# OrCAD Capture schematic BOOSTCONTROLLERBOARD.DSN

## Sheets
1 7 I2C Devices: size B; title: Controller Board: I2C Devices; rev: B; company: MBARI; note: 10021168
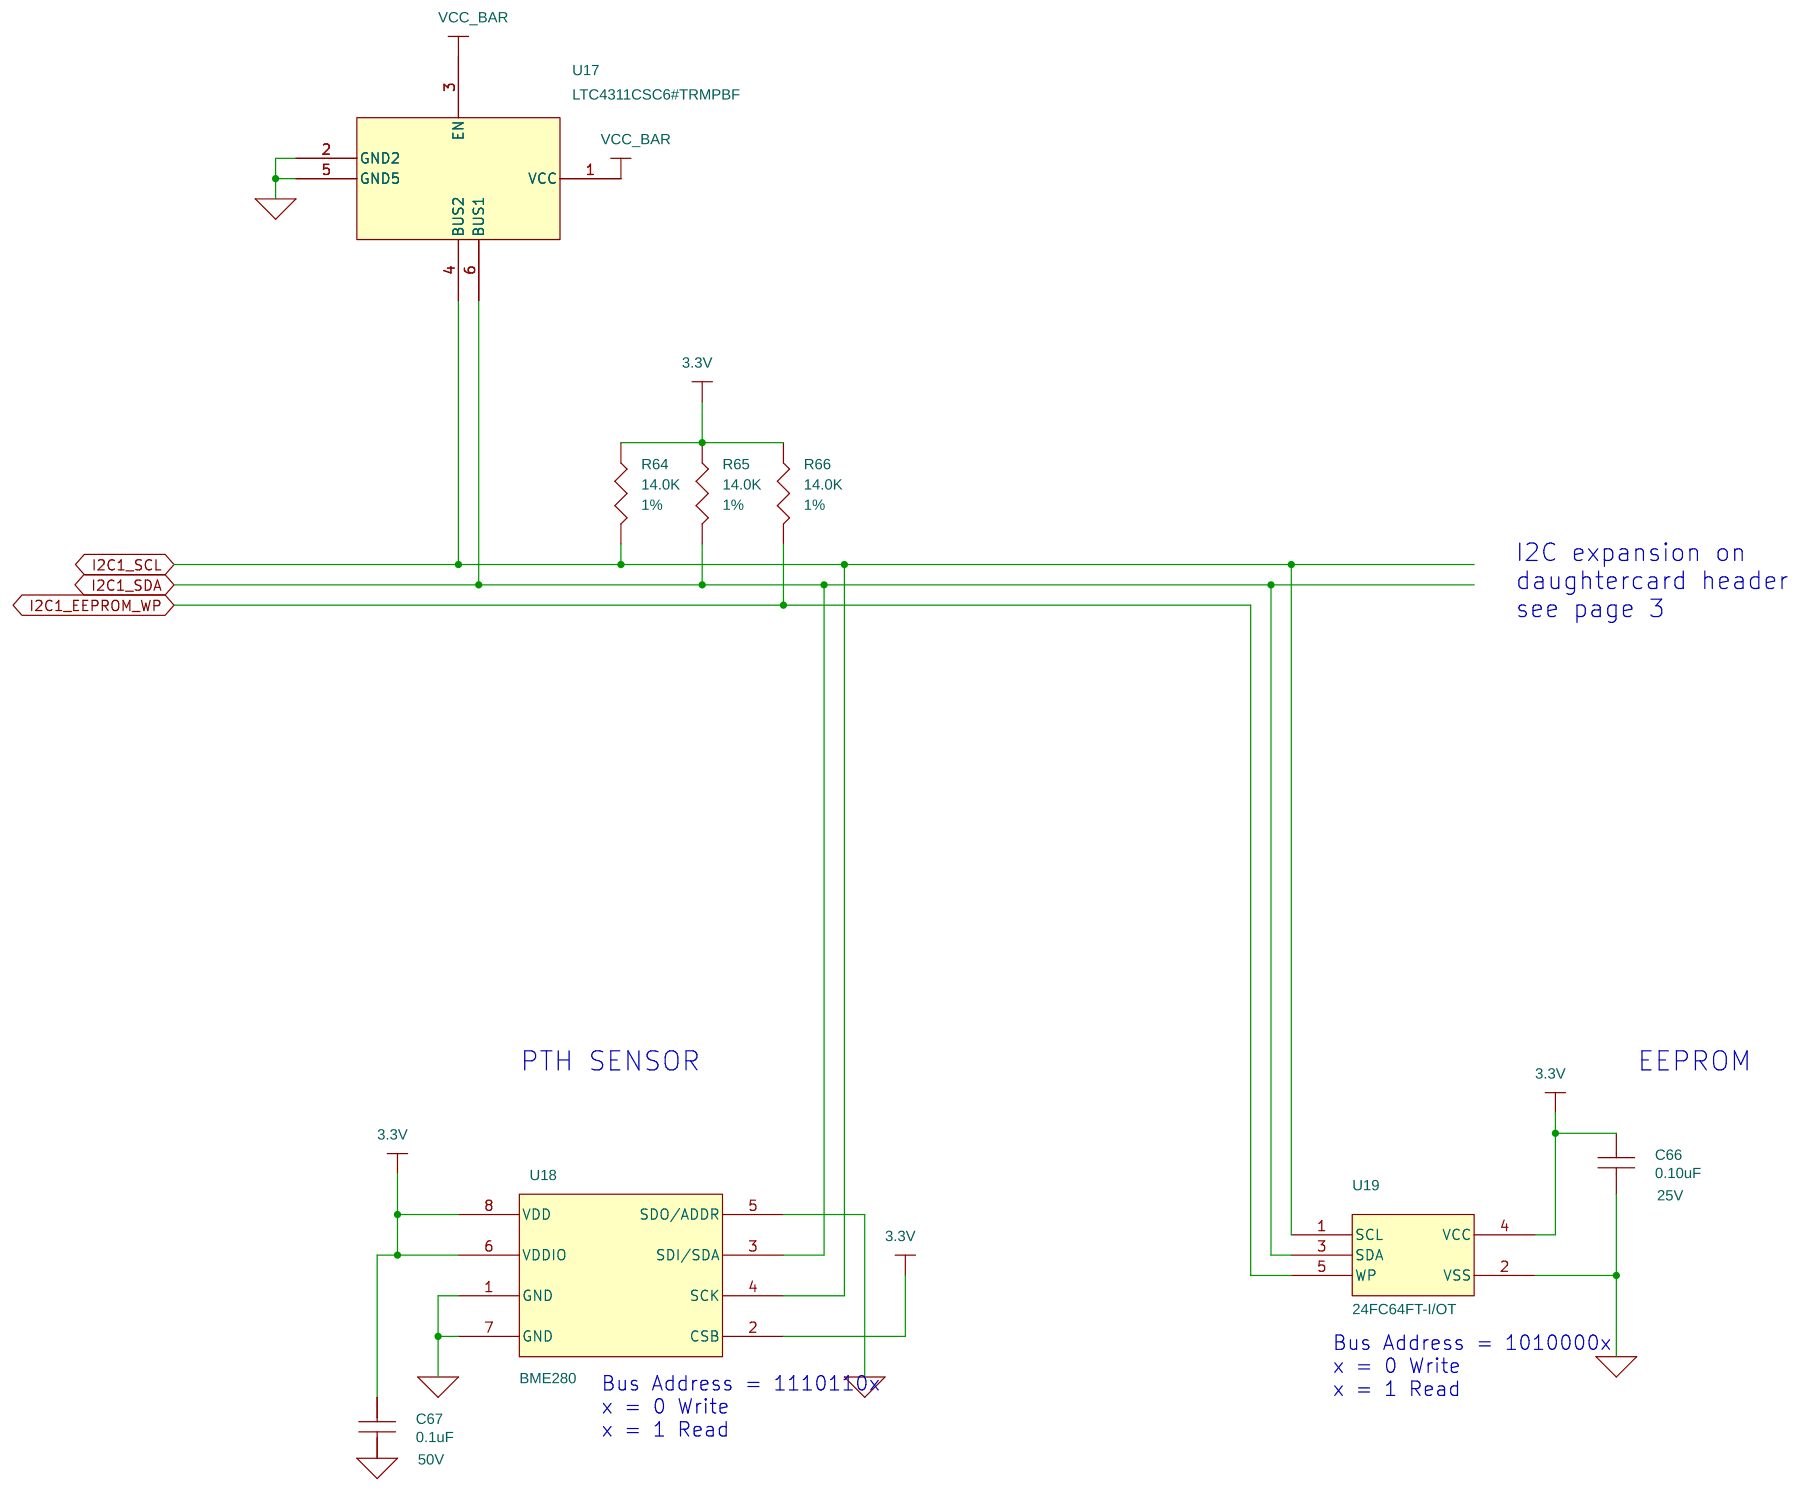
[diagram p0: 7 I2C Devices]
2 2 Power Supply: size C; title: Controller Board: Power Supply
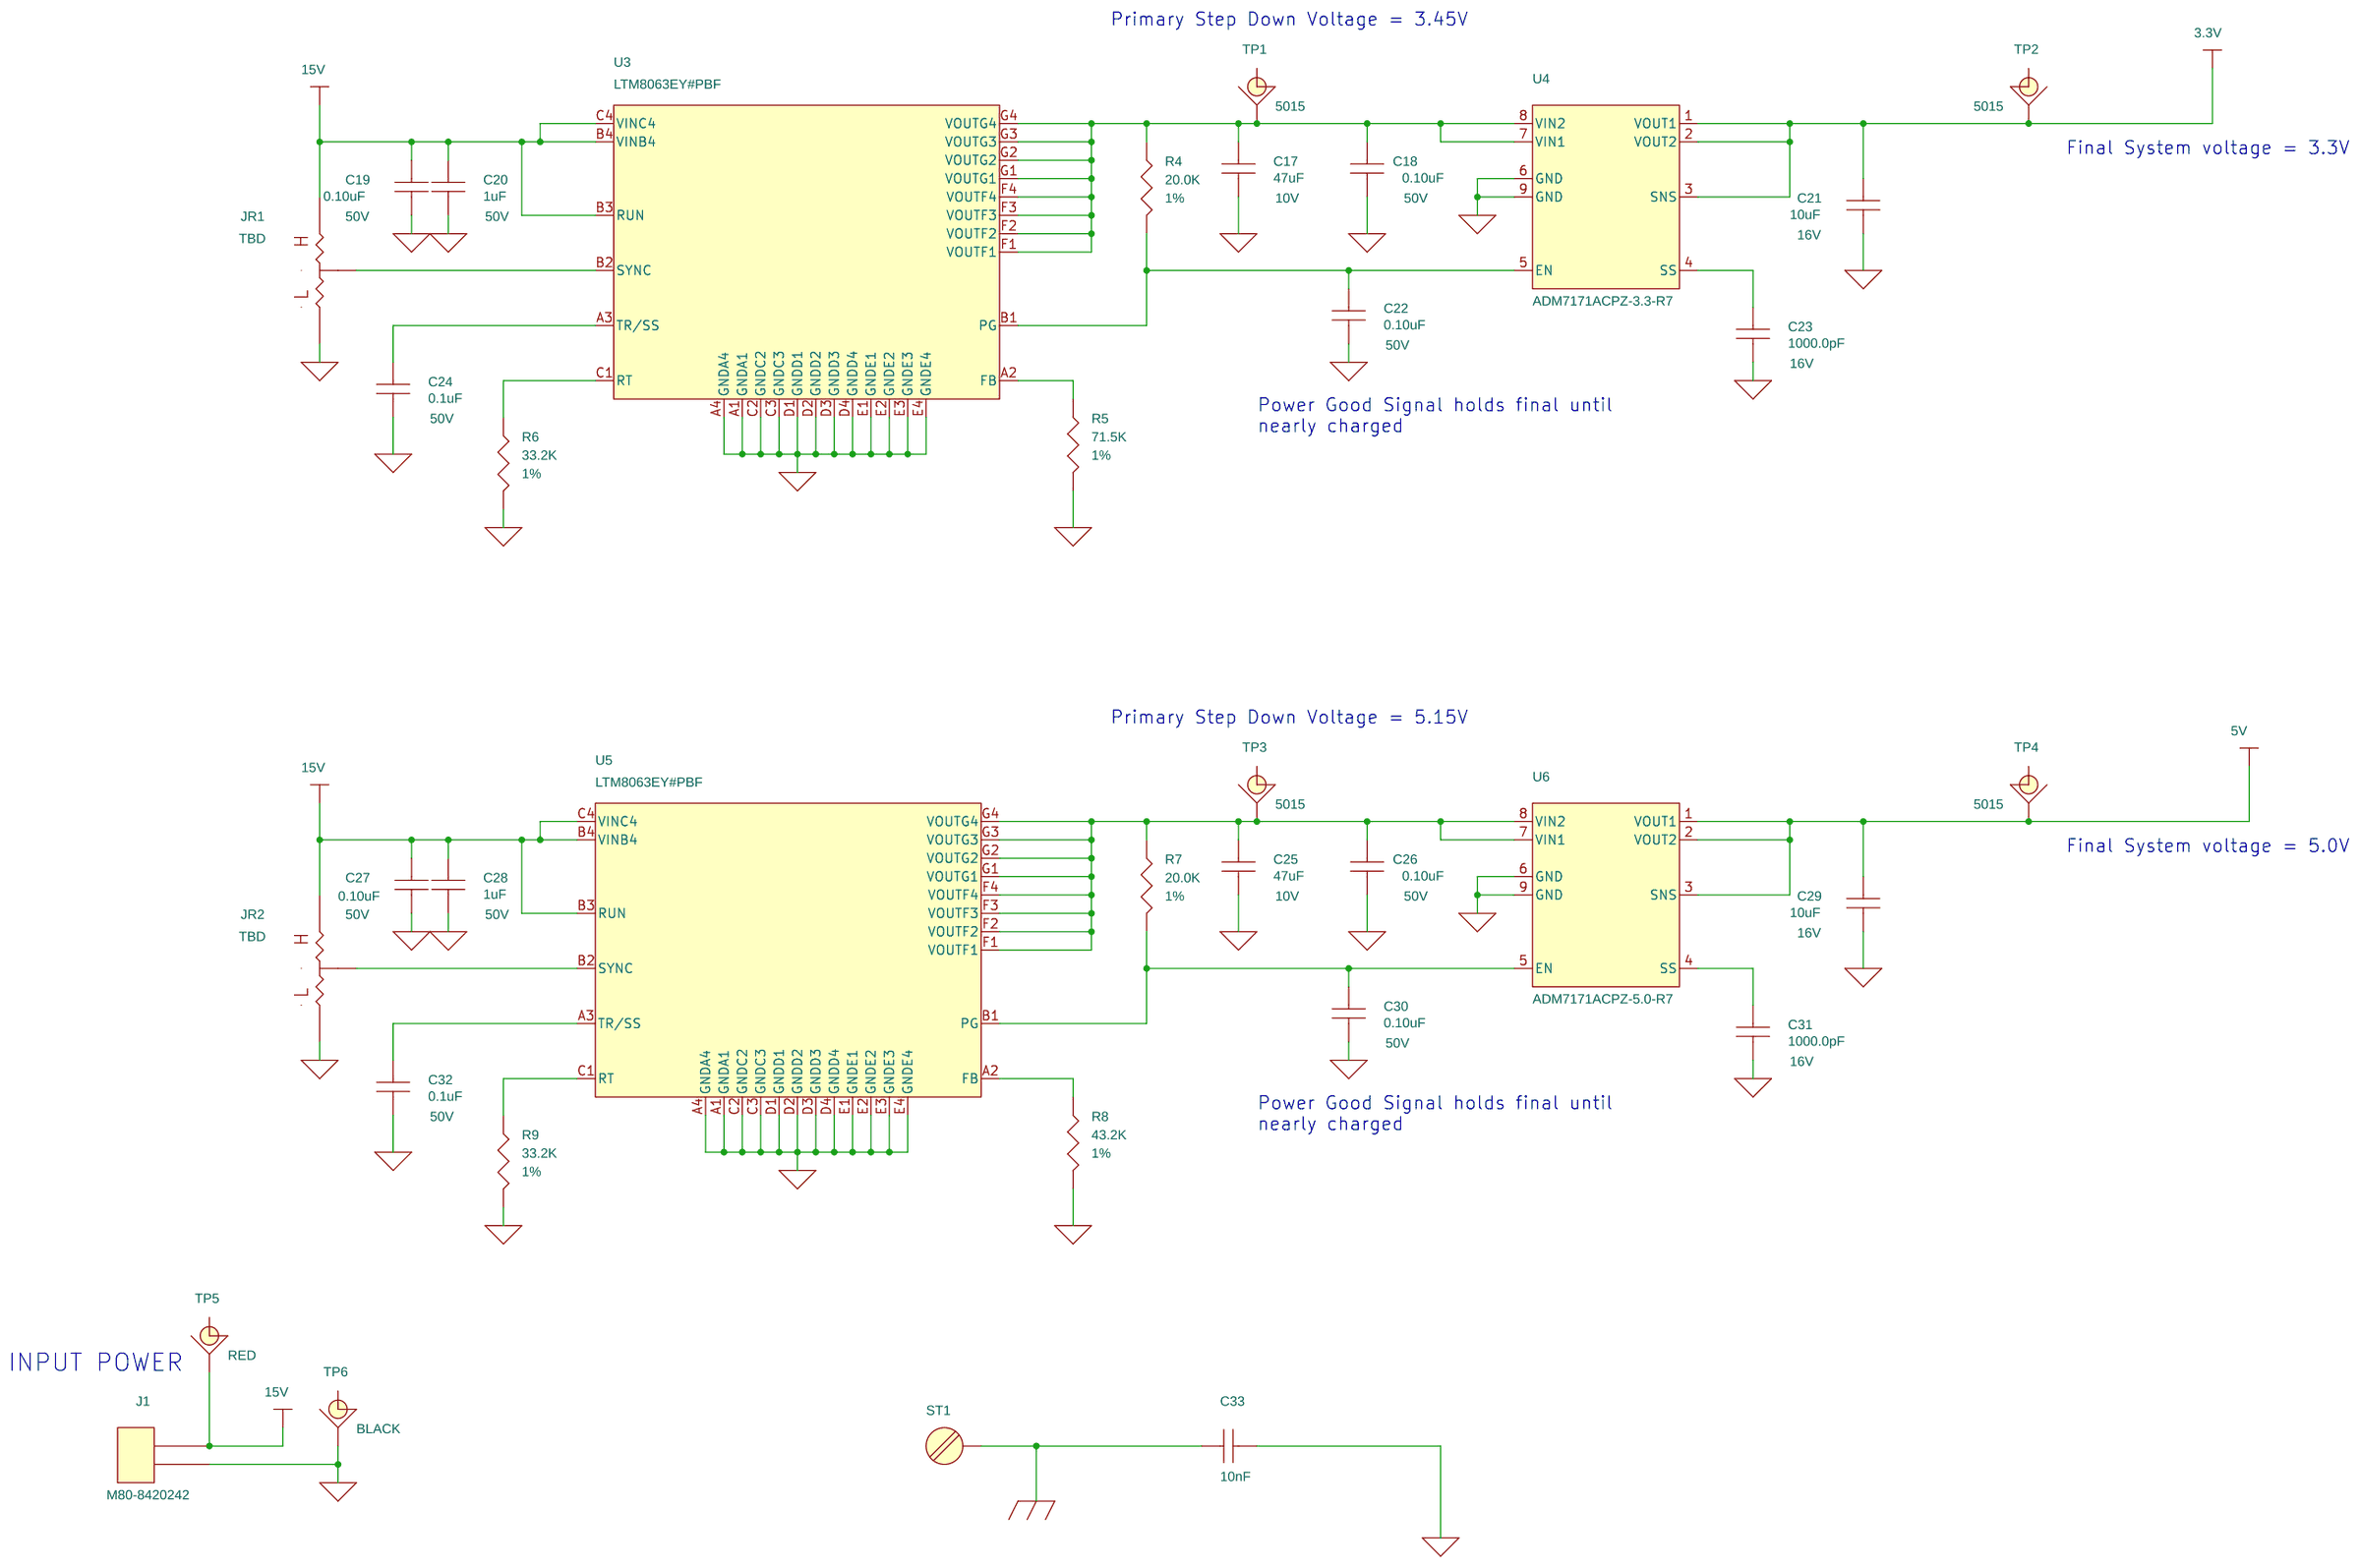
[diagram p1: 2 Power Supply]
3 1 Microcontroller: size Custom; title: Controller Board: Microcontroller
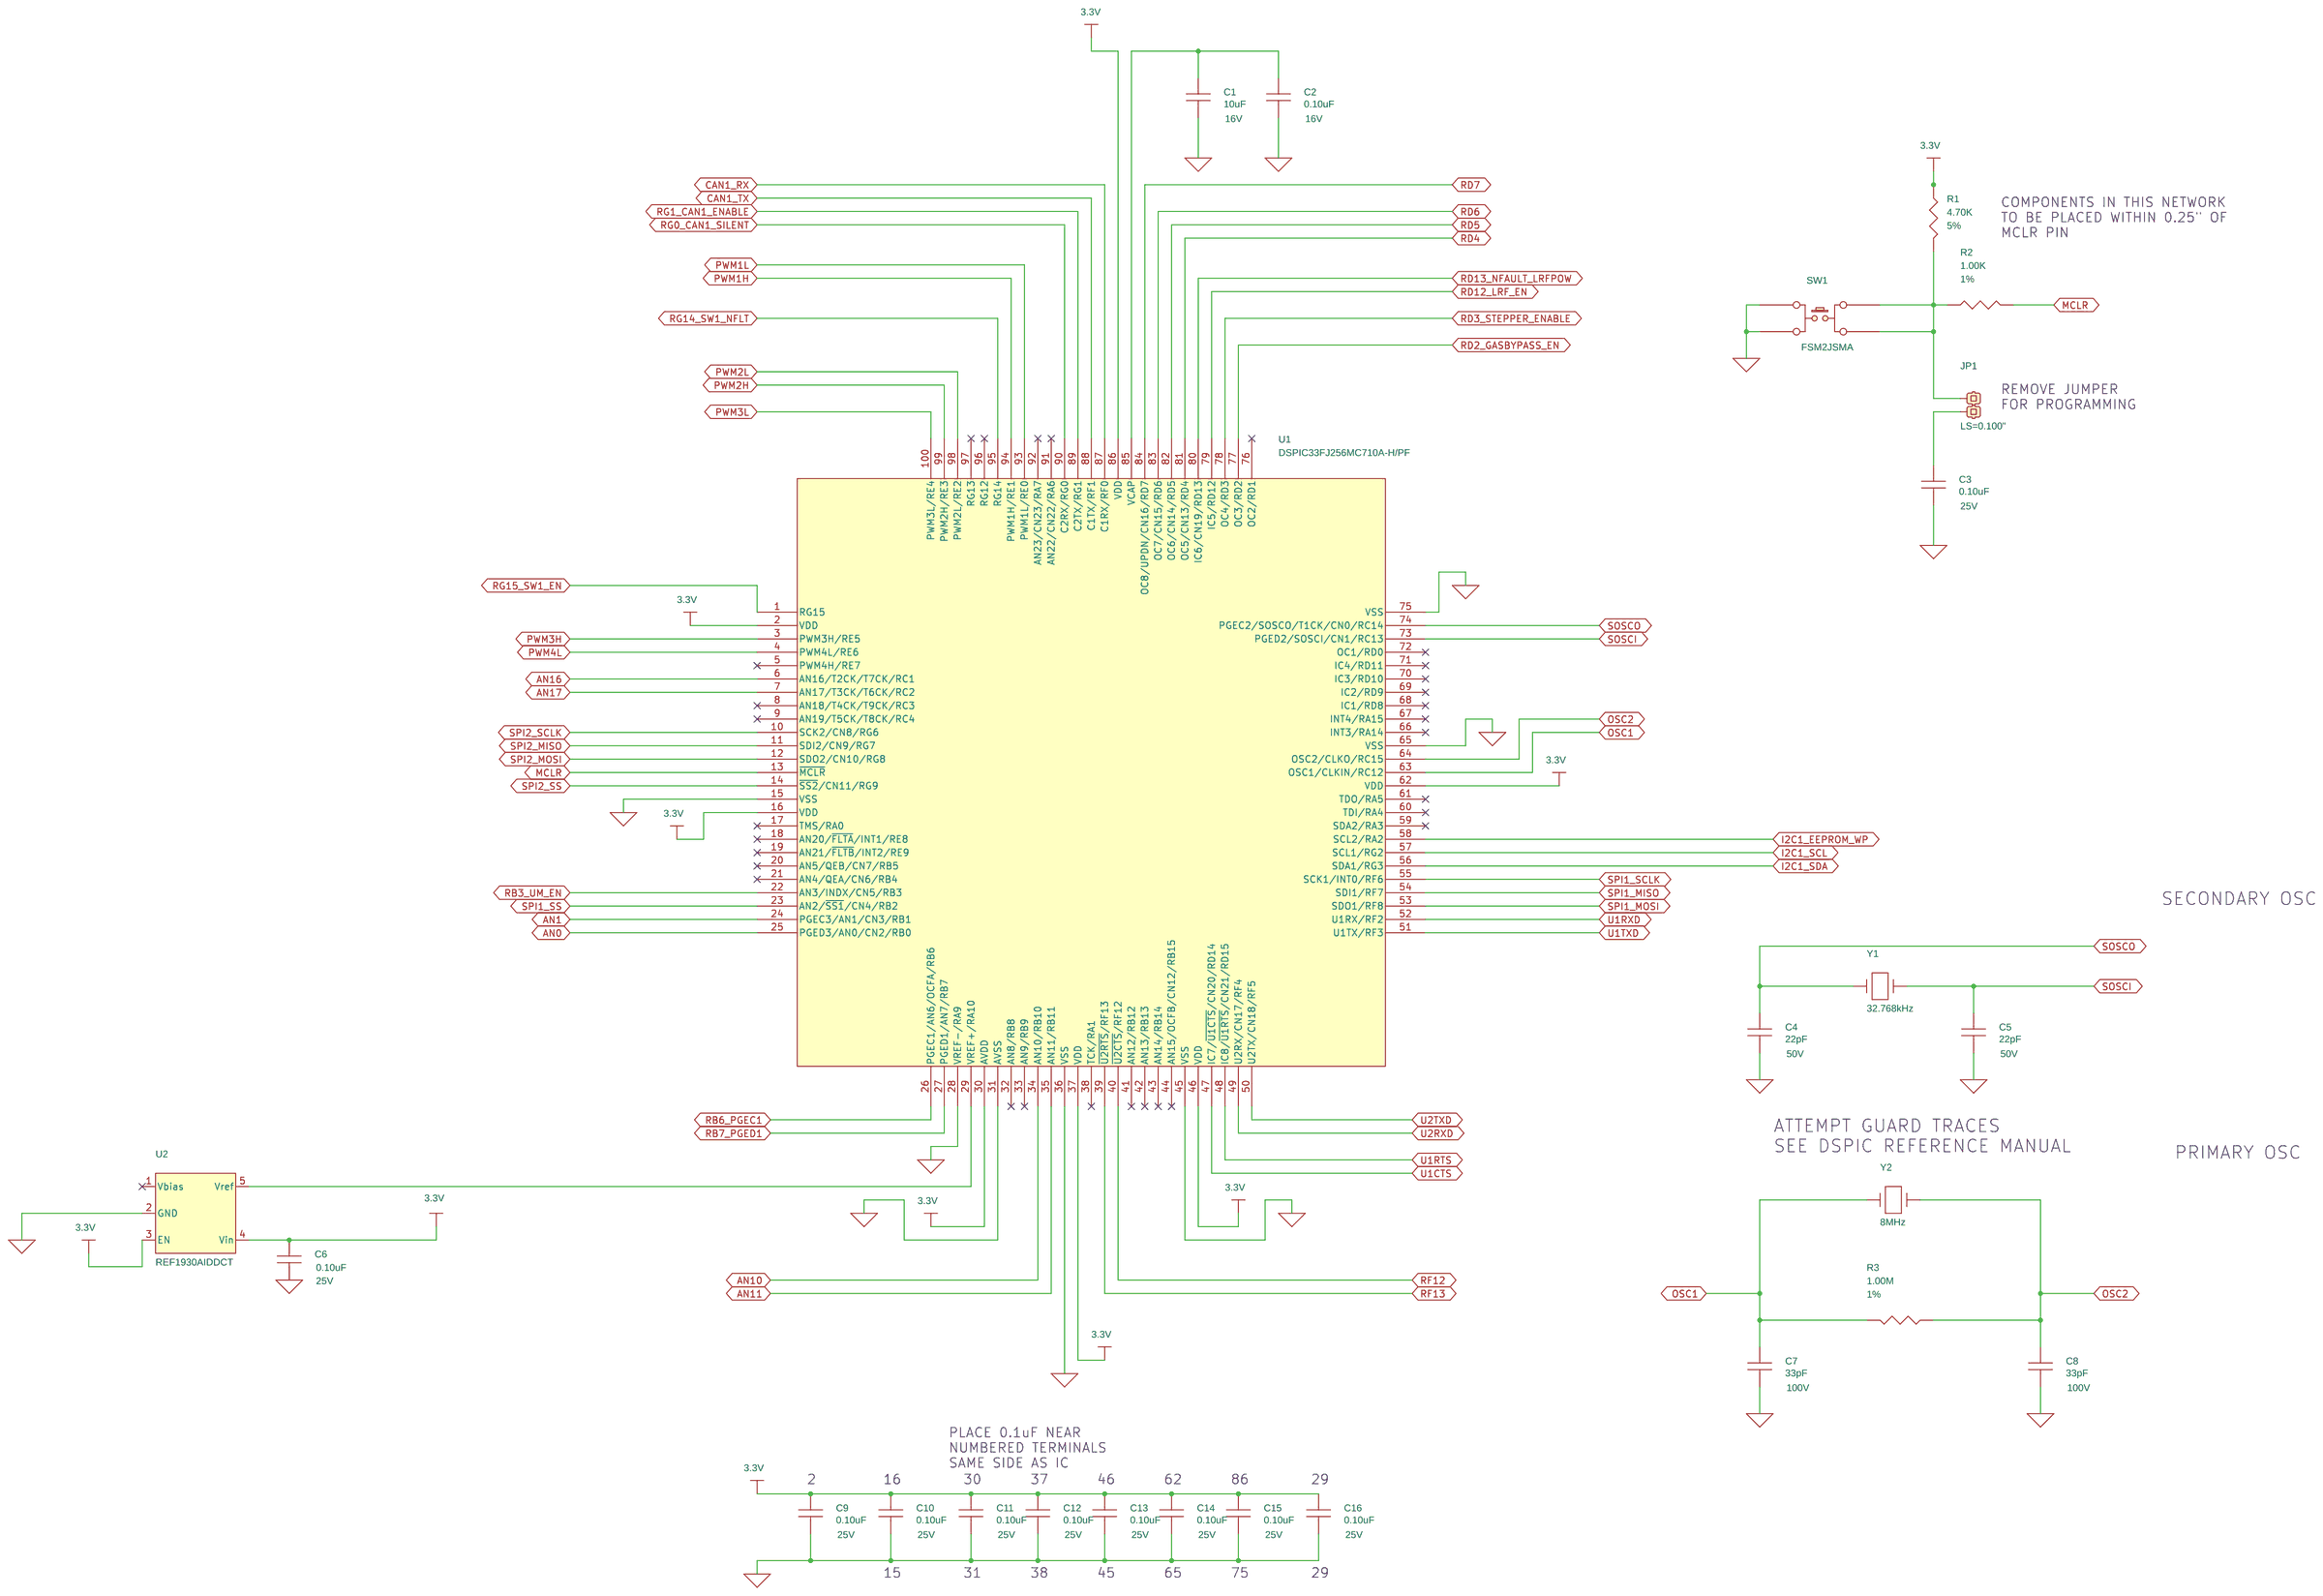
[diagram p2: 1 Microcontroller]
4 3 Telemetry: size Custom; title: Controller Board: Telemetry
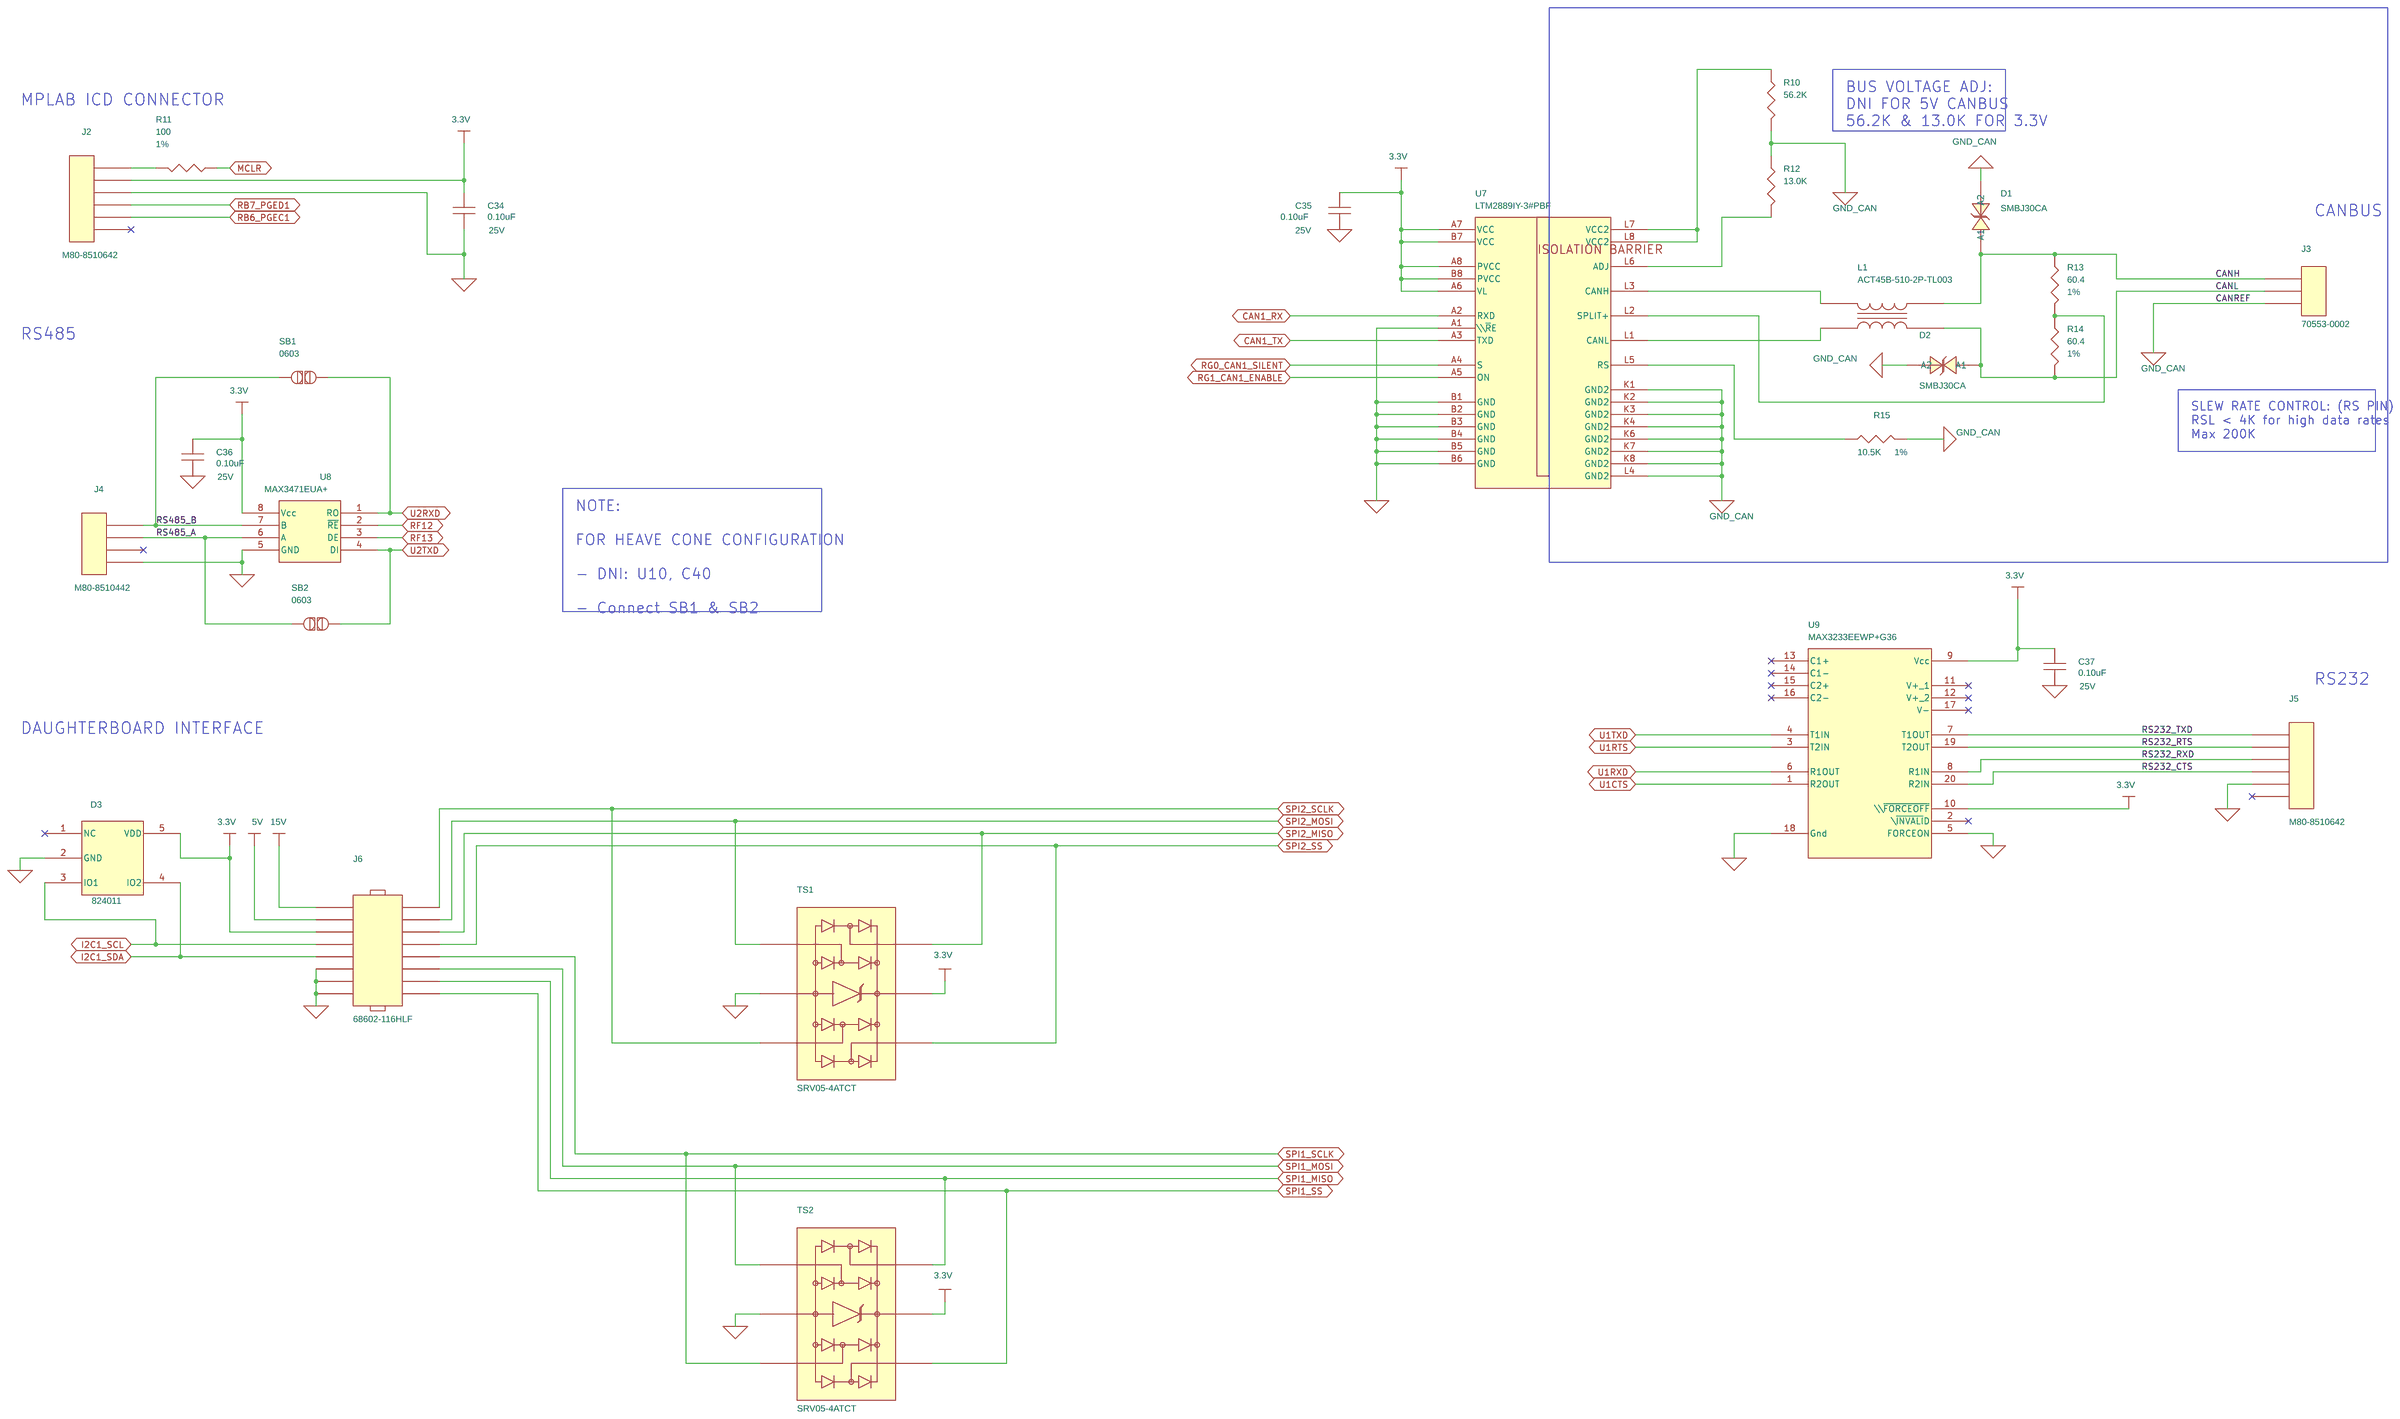
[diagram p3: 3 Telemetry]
5 5 Analog Inputs Sensors: size Custom; title: Controller Board: Sensor Inputs
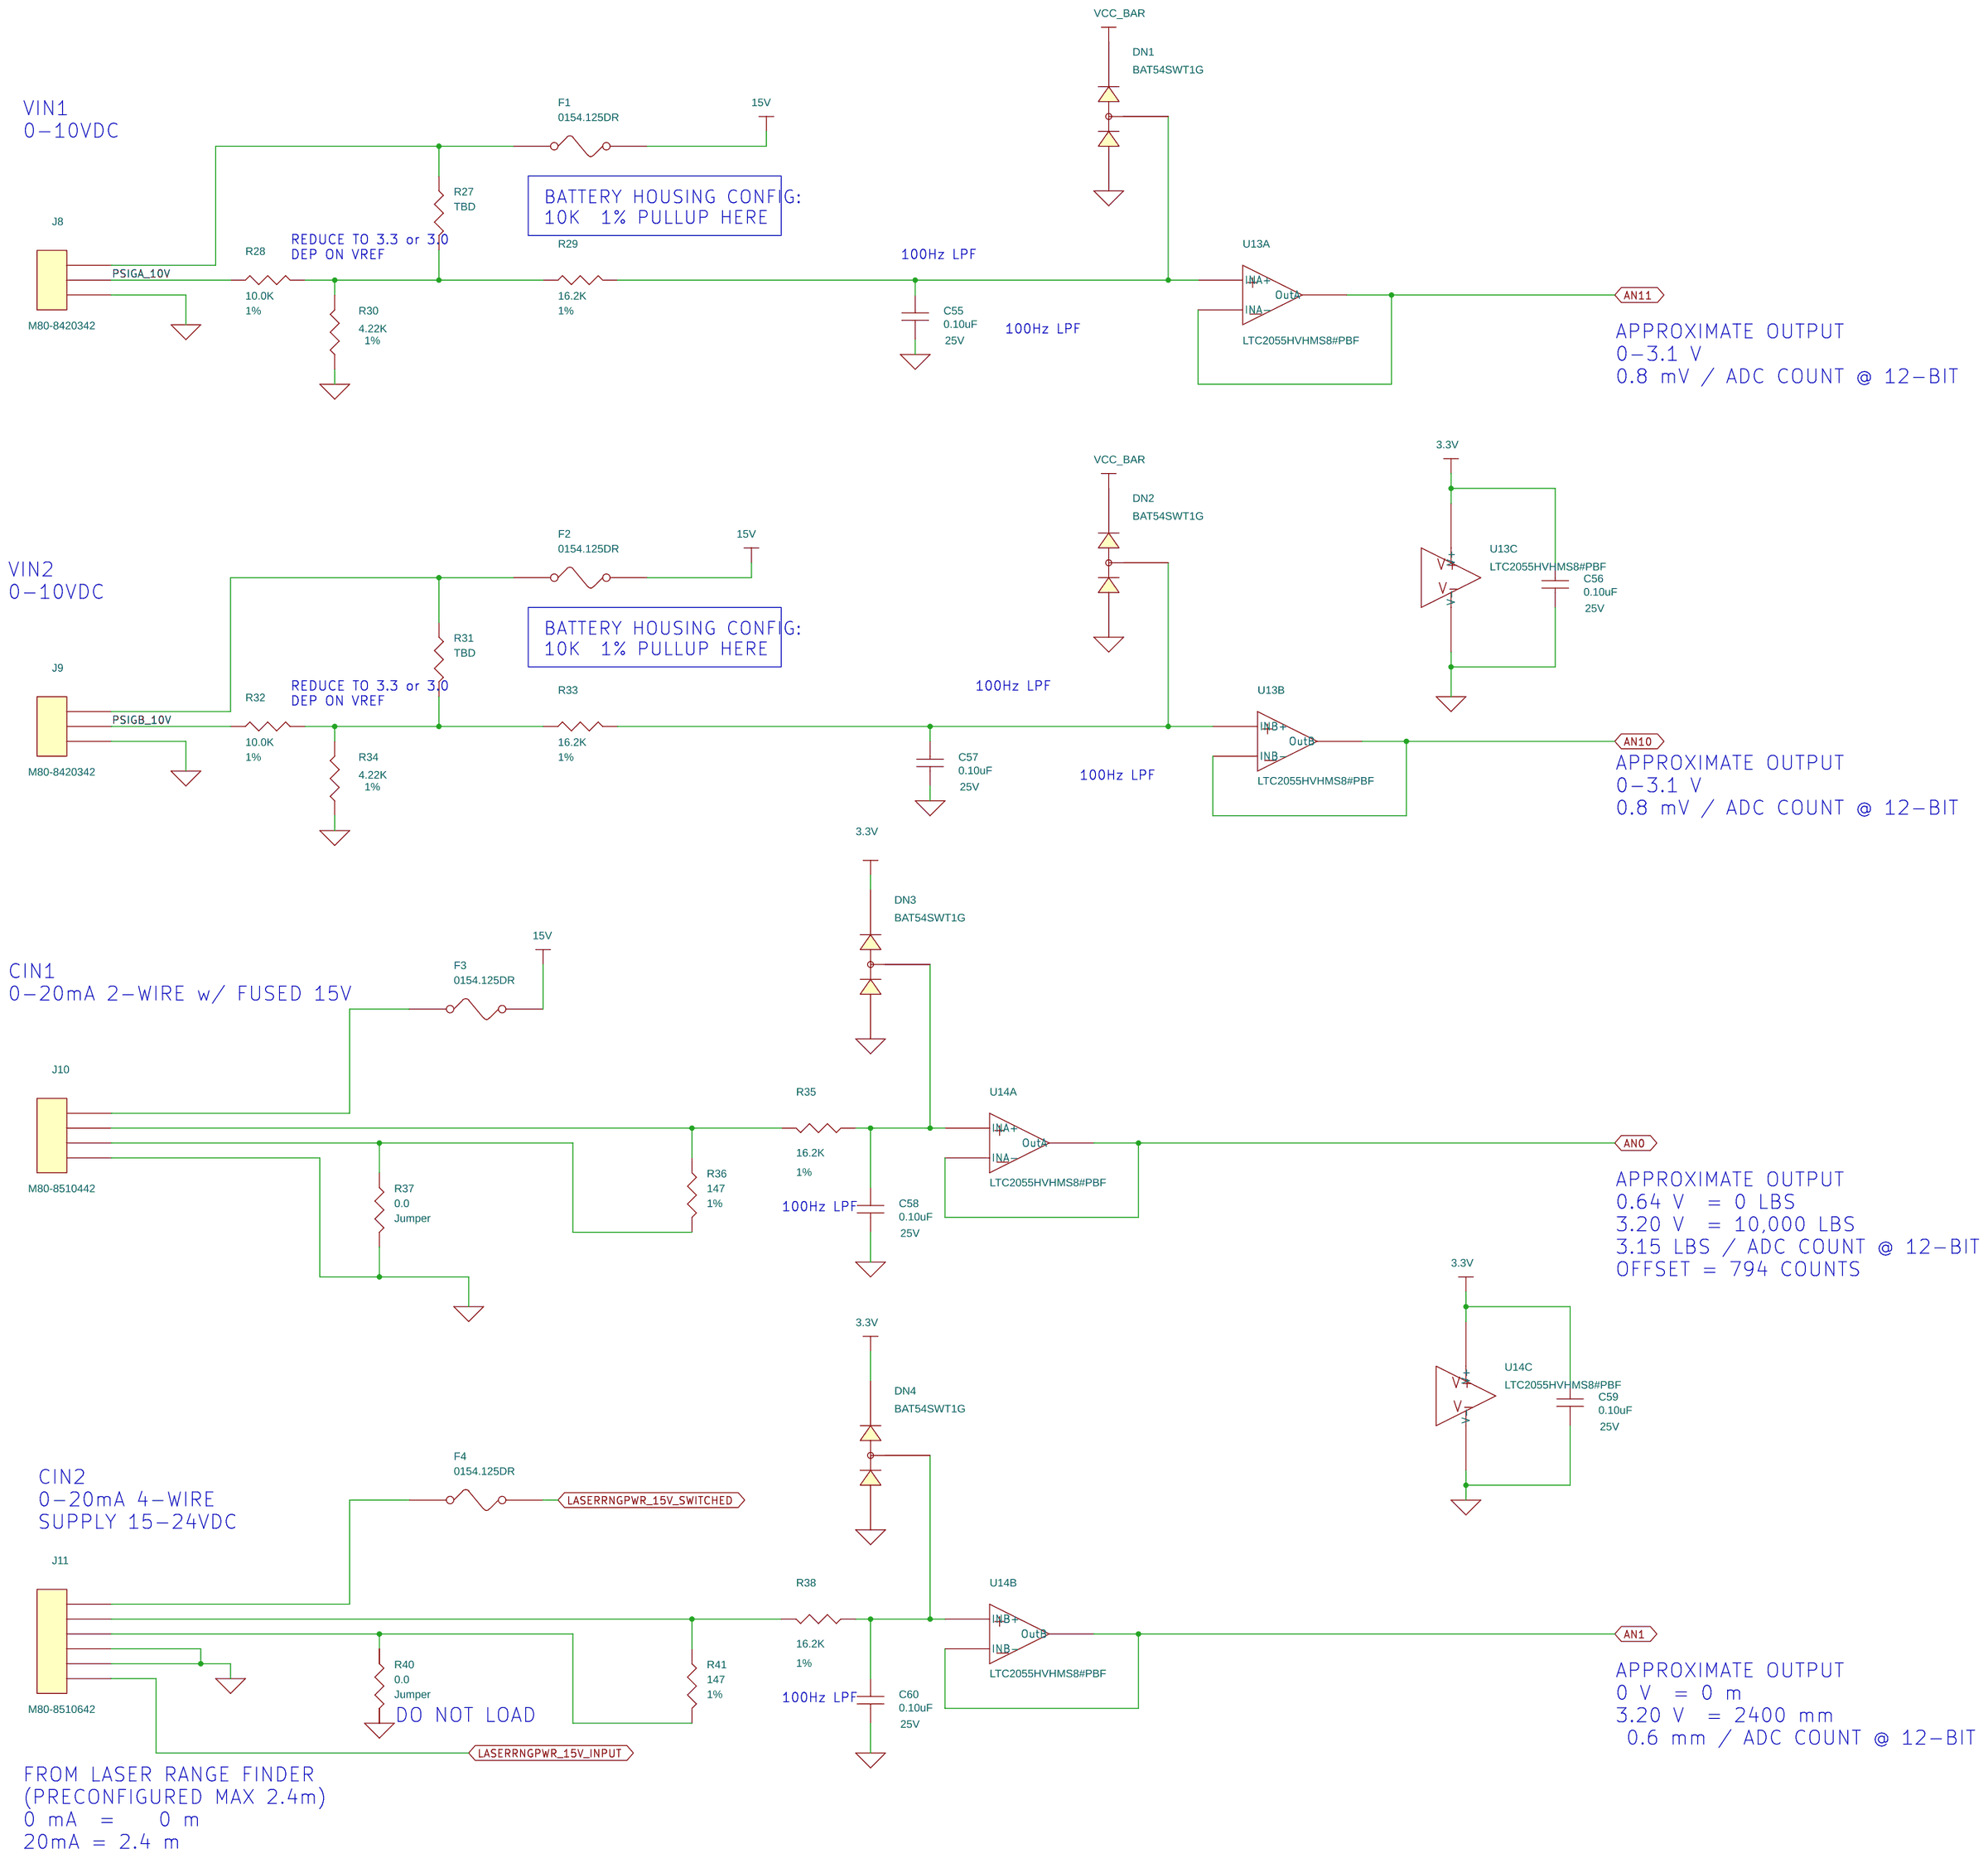
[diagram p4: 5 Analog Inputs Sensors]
6 6 Digital I/O: size Custom; title: Controller Board: Digital IO
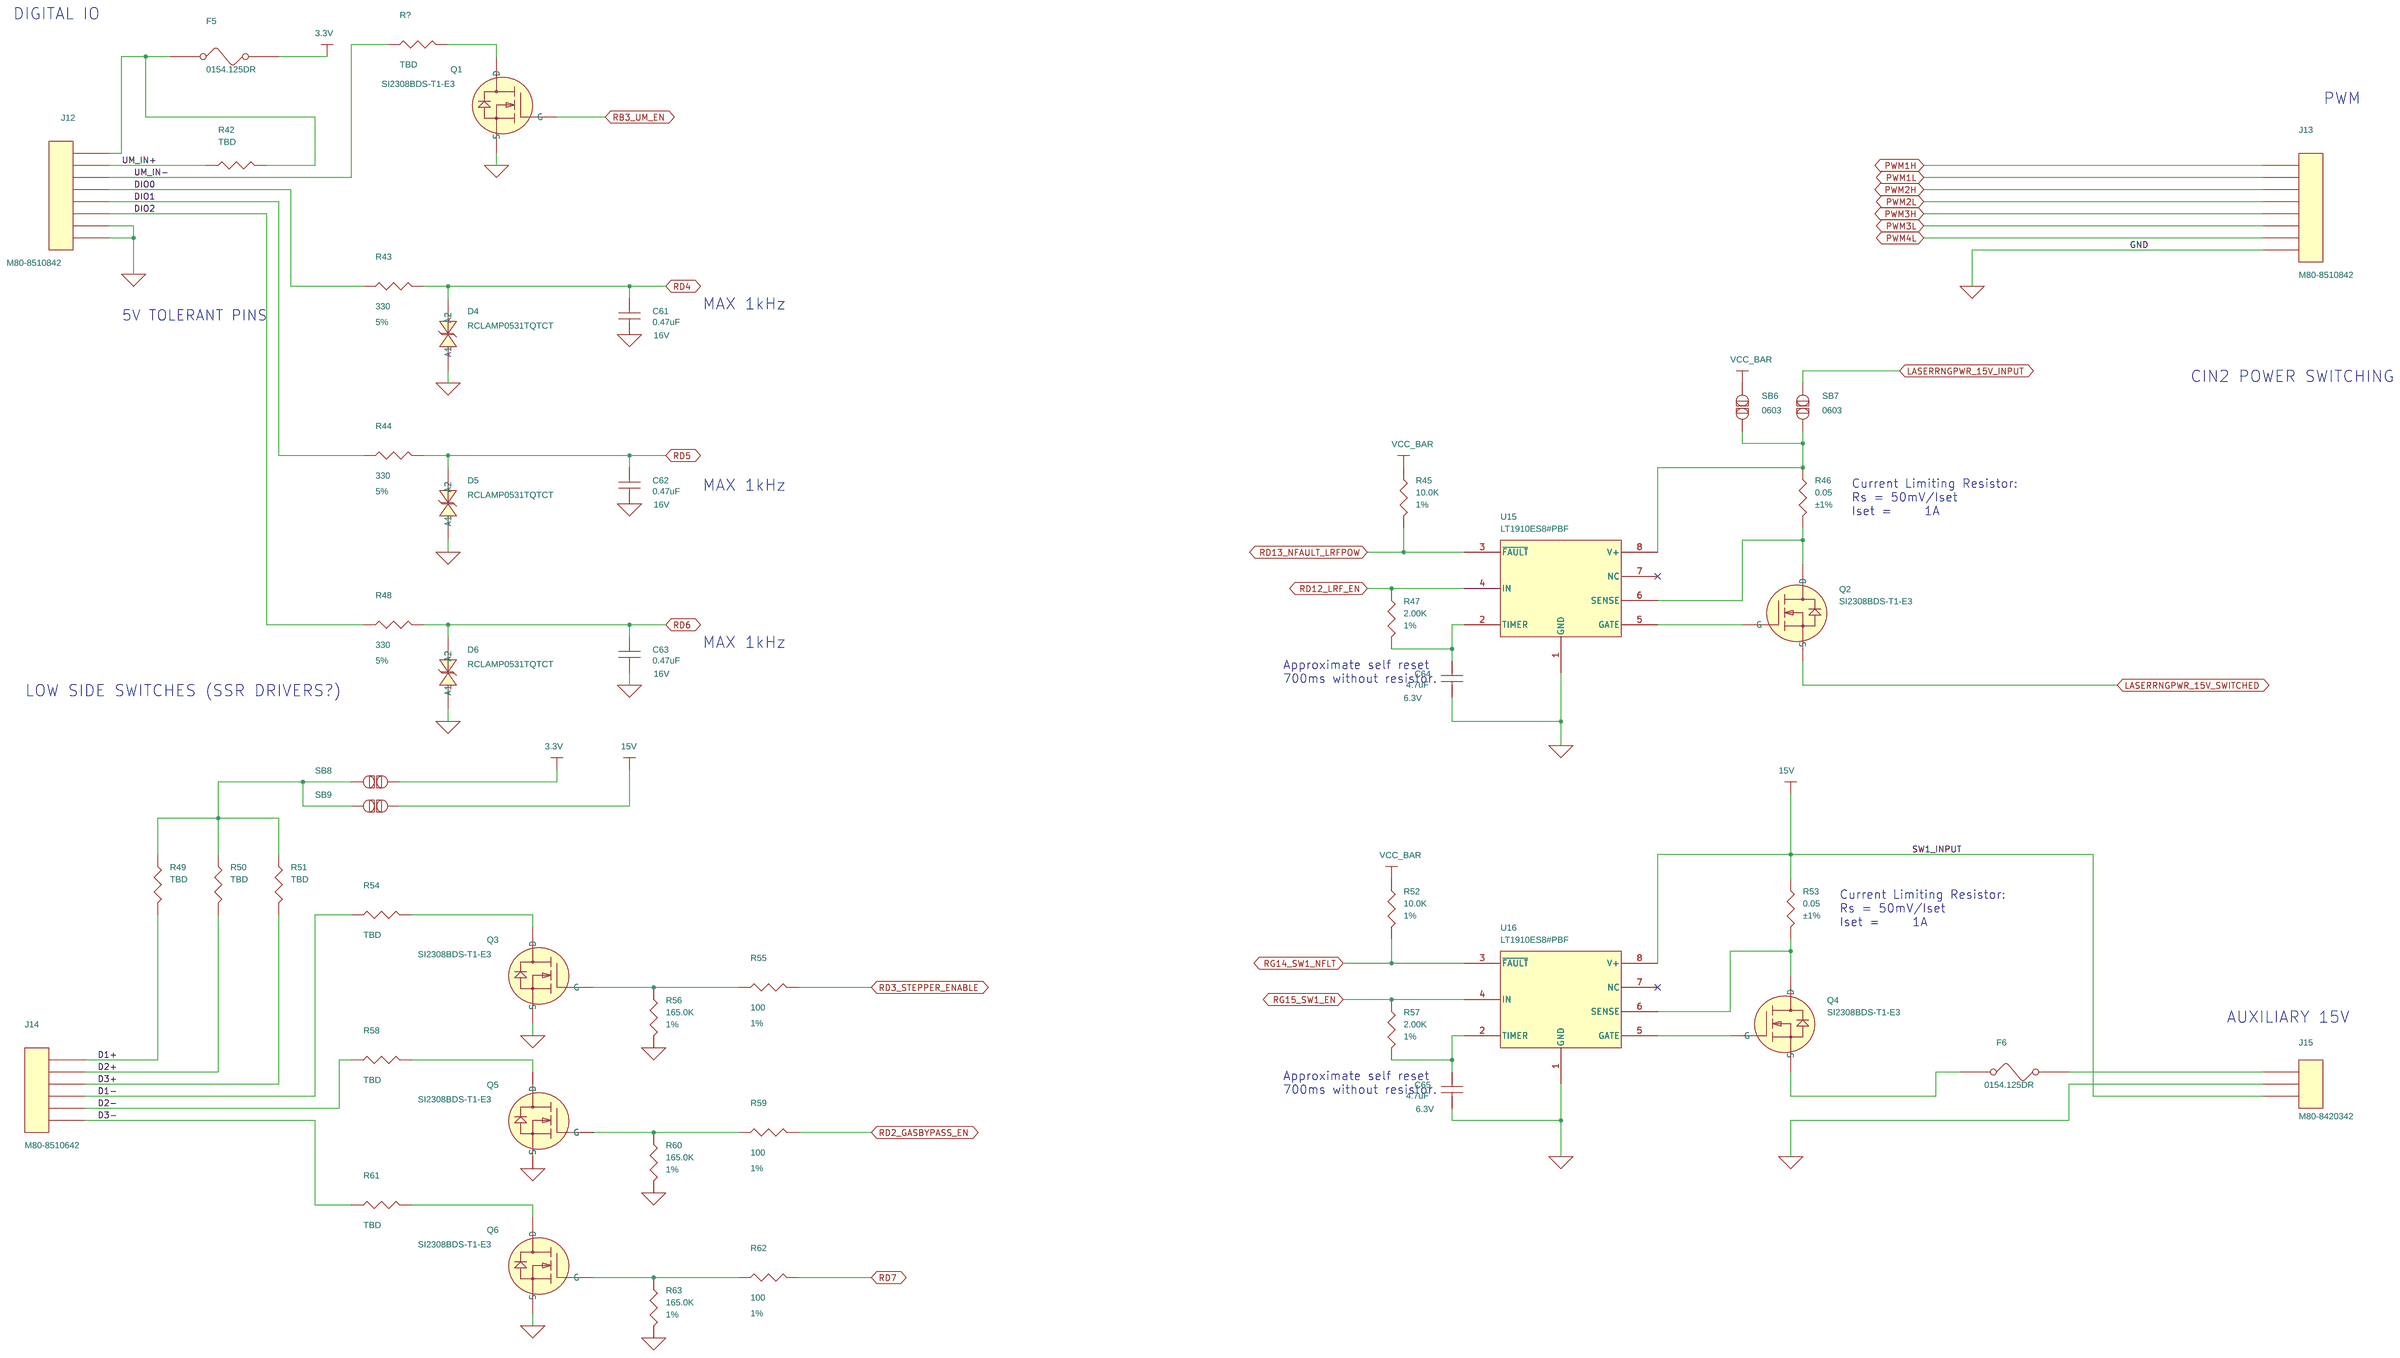
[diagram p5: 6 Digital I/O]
7 4 Analog Inputs V/I Monitors: size Custom; title: Controller Board: Filtered Inputs
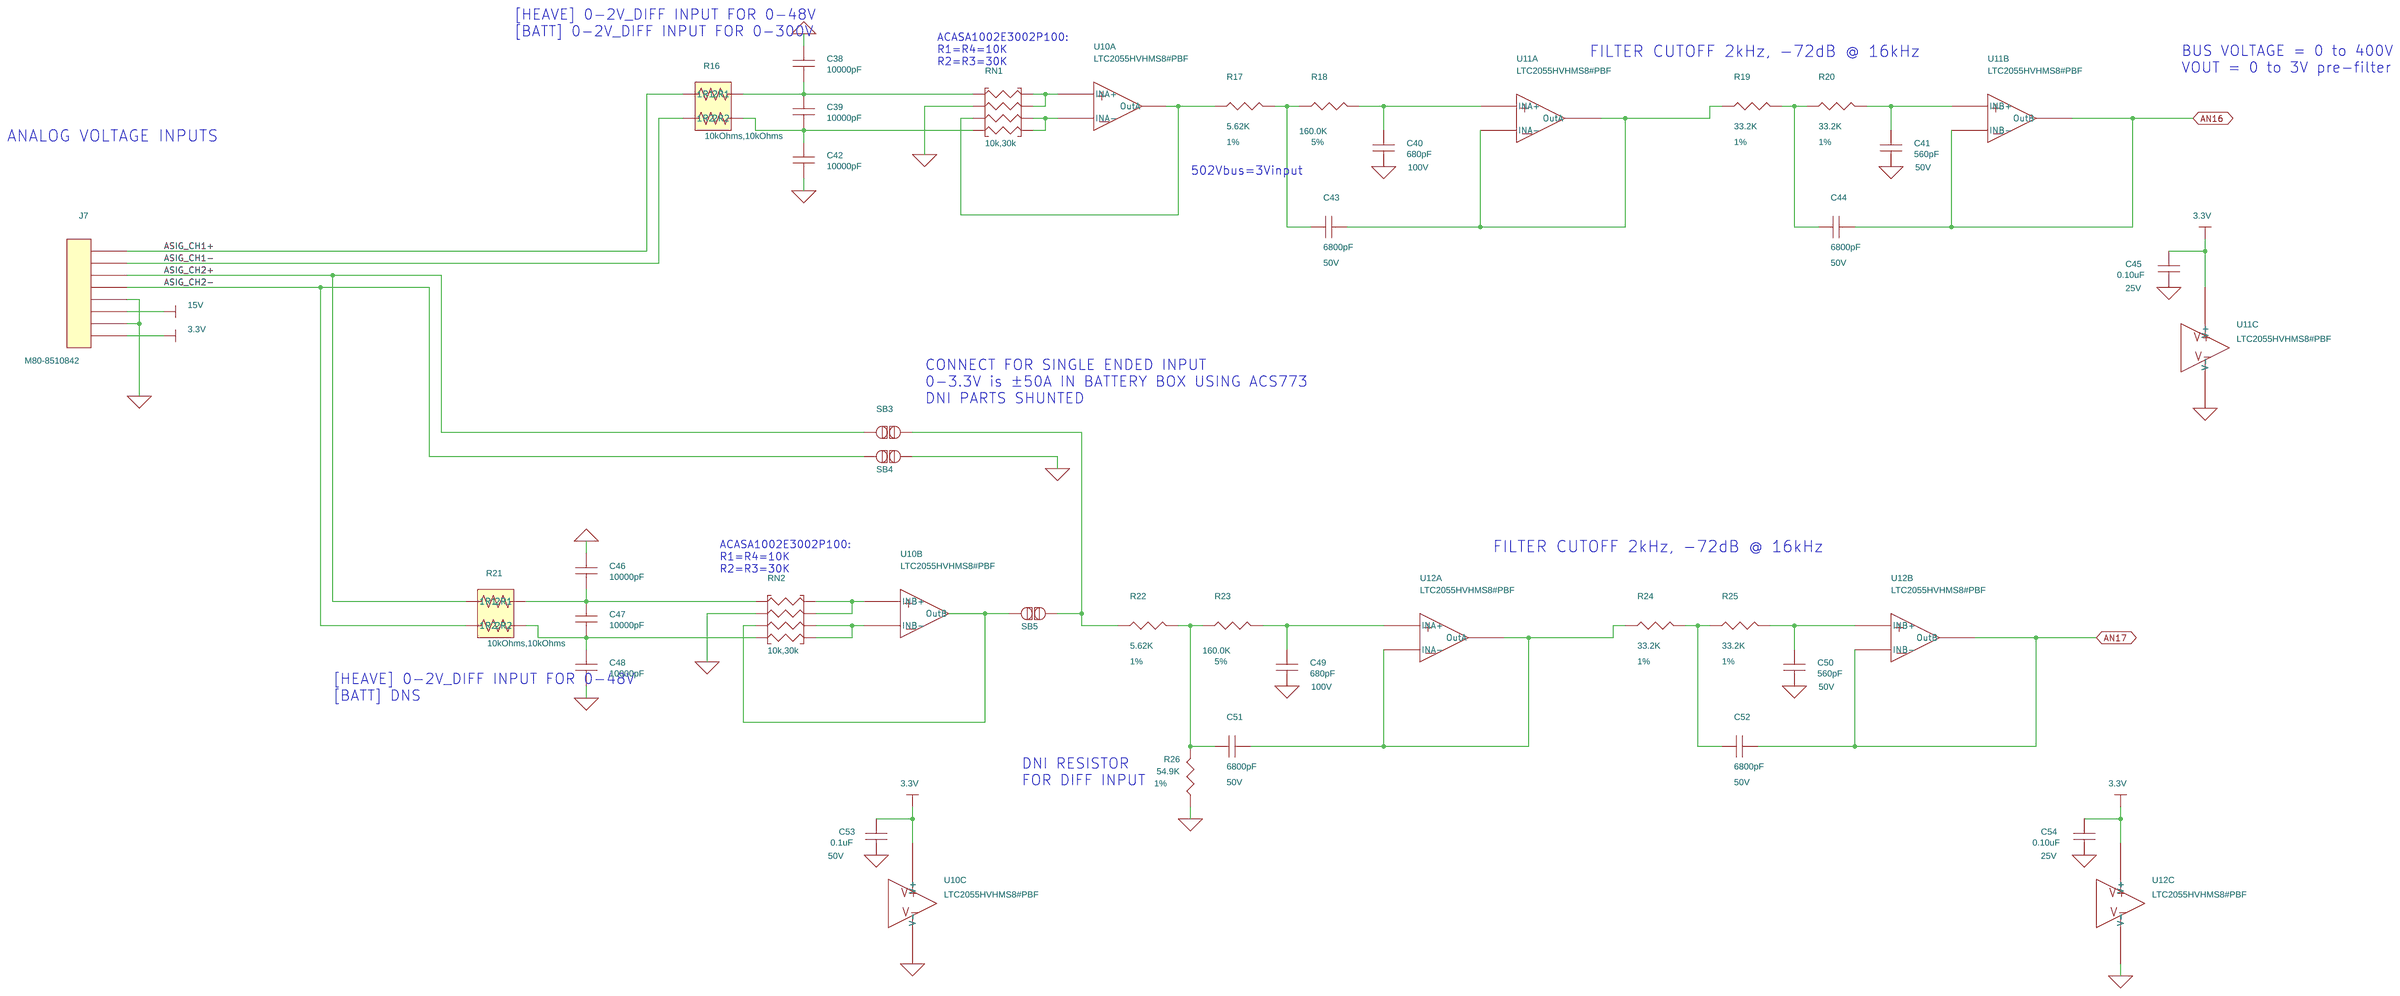
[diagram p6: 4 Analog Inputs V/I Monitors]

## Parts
sheet 1 Microcontroller
C1  10uF  [CAPC2012X135N]
C2  0.10uF  [CAPC1608X87N]
C3  0.10uF  [CAPC1608X87N]
C4  22pF  [CAPC1608X90N_G100]
C5  22pF  [CAPC1608X90N_G100]
C6  0.10uF  [CAPC1608X87N]
C7  33pF  [CAPC1608X90N]
C8  33pF  [CAPC1608X90N]
C9  0.10uF  [CAPC1608X87N]
C10  0.10uF  [CAPC1608X87N]
C11  0.10uF  [CAPC1608X87N]
C12  0.10uF  [CAPC1608X87N]
C13  0.10uF  [CAPC1608X87N]
C14  0.10uF  [CAPC1608X87N]
C15  0.10uF  [CAPC1608X87N]
C16  0.10uF  [CAPC1608X87N]
JP1  LS=0.100"  [HDRV2W64P254_2X1_508X254H1363B]
R1  4.70K  [RESC1608X50N]
R2  1.00K  [RESC1608X50N]
R3  1.00M  [RESC2012X50N]
SW1  FSM2JSMA  [SOIC450P1000X459R-4N]
U1  DSPIC33FJ256MC710A-H/PF  [QFP50P1600X1600X120-100L30N]
U2  REF1930AIDDCT  [SOT95P280X110-5L30N]
Y1  32.768kHz  [OSCCC150X320X90-2N]
Y2  8MHz  [XTALSC500X500X135-2N]
sheet 2 Power Supply
C17  47uF  [CAPC3225X270N]
C18  0.10uF  [AVX_LICC-0508-A_CAPC]
C19  0.10uF  [AVX_LICC-0508-A_CAPC]
C20  1uF  [MURATA_GCM31M-1206_CAPC]
C21  10uF  [CAPC2012X135N]
C22  0.10uF  [CAPC1608X87N]
C23  1000.0pF  [CAPC2012X88N]
C24  0.1uF  [MURATA_GCM188-0603_CAPC]
C25  47uF  [CAPC3225X270N]
C26  0.10uF  [AVX_LICC-0508-A_CAPC]
C27  0.10uF  [AVX_LICC-0508-A_CAPC]
C28  1uF  [MURATA_GCM31M-1206_CAPC]
C29  10uF  [CAPC2012X135N]
C30  0.10uF  [CAPC1608X87N]
C31  1000.0pF  [CAPC2012X88N]
C32  0.1uF  [MURATA_GCM188-0603_CAPC]
C33  10nF  [VISHAY_MKP338_175X50X110_CAPRR]
J1  M80-8420242  [HARWIN_M80-842_2PIN]
JR1  TBD  [MISC_0603-3P-JMPR]
JR2  TBD  [MISC_0603-3P-JMPR]
R4  20.0K  [RESC2012X50N]
R5  71.5K  [RESC1608X50N]
R6  33.2K  [RESC1608X50N]
R7  20.0K  [RESC2012X50N]
R8  43.2K  [RESC1608X50N]
R9  33.2K  [RESC1608X50N]
ST1  #4 SCREW TERMINAL  [MNT_C220H125]
TP1  5015  [TP_5015]
TP2  5015  [TP_5015]
TP3  5015  [TP_5015]
TP4  5015  [TP_5015]
TP5  RED  [TP_KEYSTONE_5000s_MINI]
TP6  BLACK  [TP_KEYSTONE_5000s_MINI]
U3  LTM8063EY#PBF  [LINEAR_BGA28]
U4  ADM7171ACPZ-3.3-R7  [SON50P300X300X80-9T170X254N]
U5  LTM8063EY#PBF  [LINEAR_BGA28]
U6  ADM7171ACPZ-5.0-R7  [SON50P300X300X80-9T170X254N]
sheet 3 Telemetry
C34  0.10uF  [CAPC1608X87N]
C35  0.10uF  [CAPC1608X87N]
C36  0.10uF  [CAPC1608X87N]
C37  0.10uF  [CAPC1608X87N]
D1  SMBJ30CA  [LITTELFUSE-SMB_DIOM-NP]
D2  SMBJ30CA  [LITTELFUSE-SMB_DIOM-NP]
D3  824011  [SOT95P280X145-5L30N]
J2  M80-8510642  [HARWIN_M80-851_6PIN]
J3  70553-0002  [MOLEX_70553-3PIN]
J4  M80-8510442  [HARWIN_M80-851_4PIN]
J5  M80-8510642  [HARWIN_M80-851_6PIN]
J6  68602-116HLF  [HDRV16W64P254_2X8_858H]
L1  ACT45B-510-2P-TL003  [TDK_ACT45B]
R10  56.2K  [RESC1608X50N]
R11  100  [RESC2012X50N]
R12  13.0K  [RESC1608X50N]
R13  60.4  [RESC3216X60N]
R14  60.4  [RESC3216X60N]
R15  10.5K  [RESC1608X50N]
SB1  0603  [MISC_JUMPER_SM0603]
SB2  0603  [MISC_JUMPER_SM0603]
TS1  SRV05-4ATCT  [SOT95P280X145-6N]
TS2  SRV05-4ATCT  [SOT95P280X145-6N]
U7  LTM2889IY-3#PBF  [LINEAR_BGA32]
U8  MAX3471EUA+  [SOP65P490X110-8L25N]
U9  MAX3233EEWP+G36  [SOIC127P1032X265-20N]
sheet 4 Analog Inputs V/I Monitors
C38  10000pF  [PANASONIC_ECWU_0805-J2_CAPC]
C39  10000pF  [PANASONIC_ECWU_0805-J2_CAPC]
C40  680pF  [CAPC2012X88N]
C41  560pF  [CAPC1608X90N]
C42  10000pF  [PANASONIC_ECWU_0805-J2_CAPC]
C43  6800pF  [CAPC2012X90N]
C44  6800pF  [CAPC2012X90N]
C45  0.10uF  [CAPC1608X87N]
C46  10000pF  [PANASONIC_ECWU_0805-J2_CAPC]
C47  10000pF  [PANASONIC_ECWU_0805-J2_CAPC]
C48  10000pF  [PANASONIC_ECWU_0805-J2_CAPC]
C49  680pF  [CAPC2012X88N]
C50  560pF  [CAPC1608X90N]
C51  6800pF  [CAPC2012X90N]
C52  6800pF  [CAPC2012X90N]
C53  0.1uF  [CAPC2013X94N]
C54  0.10uF  [CAPC1608X87N]
J7  M80-8510842  [HARWIN_M80-851_8PIN]
R16  10kOhms,10kOhms  [VISHAY_ACAS-0606]
R17  5.62K  [RESC2012X50N]
R18  160.0K  [RESC2012X50N]
R19  33.2K  [RESC2012X50N]
R20  33.2K  [RESC2012X50N]
R21  10kOhms,10kOhms  [VISHAY_ACAS-0606]
R22  5.62K  [RESC2012X50N]
R23  160.0K  [RESC2012X50N]
R24  33.2K  [RESC2012X50N]
R25  33.2K  [RESC2012X50N]
R26  54.9K  [RESC1608X50N]
RN1  10k,30k  [VISHAY_ACAS-0612]
RN2  10k,30k  [VISHAY_ACAS-0612]
SB3  0603  [MISC_JUMPER_SM0603]
SB4  0603  [MISC_JUMPER_SM0603]
SB5  0603  [MISC_JUMPER_SM0603]
U10  LTC2055HVHMS8#PBF  [SOP65P490X110-8L30N]  (sections A,B,C)
U11  LTC2055HVHMS8#PBF  [SOP65P490X110-8L30N]  (sections A,B,C)
U12  LTC2055HVHMS8#PBF  [SOP65P490X110-8L30N]  (sections A,B,C)
sheet 5 Analog Inputs Sensors
C55  0.10uF  [CAPC1608X87N]
C56  0.10uF  [CAPC1608X87N]
C57  0.10uF  [CAPC1608X87N]
C58  0.10uF  [CAPC1608X87N]
C59  0.10uF  [CAPC1608X87N]
C60  0.10uF  [CAPC1608X87N]
DN1  BAT54SWT1G  [SOT65P220X100-3N_132]
DN2  BAT54SWT1G  [SOT65P220X100-3N_132]
DN3  BAT54SWT1G  [SOT65P220X100-3N_132]
DN4  BAT54SWT1G  [SOT65P220X100-3N_132]
F1  0154.125DR  [FUSM9750X381N]
F2  0154.125DR  [FUSM9750X381N]
F3  0154.125DR  [FUSM9750X381N]
F4  0154.125DR  [FUSM9750X381N]
J8  M80-8420342  [HARWIN_M80-842_3PIN]
J9  M80-8420342  [HARWIN_M80-842_3PIN]
J10  M80-8510442  [HARWIN_M80-851_4PIN]
J11  M80-8510642  [HARWIN_M80-851_6PIN]
R27  TBD  [MBARI_TBD0603_RESC]
R28  10.0K  [RESC1608X50N]
R29  16.2K  [RESC1608X50N]
R30  4.22K  [RESC1608X50N]
R31  TBD  [MBARI_TBD0603_RESC]
R32  10.0K  [RESC1608X50N]
R33  16.2K  [RESC1608X50N]
R34  4.22K  [RESC1608X50N]
R35  16.2K  [RESC1608X50N]
R36  147  [RESC1608X50N]
R37  0.0  [RESC2012X50N]
R38  16.2K  [RESC1608X50N]
R40  0.0  [RESC2012X50N]
R41  147  [RESC1608X50N]
U13  LTC2055HVHMS8#PBF  [SOP65P490X110-8L30N]  (sections A,B,C)
U14  LTC2055HVHMS8#PBF  [SOP65P490X110-8L30N]  (sections A,B,C)
sheet 6 Digital I/O
C61  0.47uF  [CAPC1608X87N]
C62  0.47uF  [CAPC1608X87N]
C63  0.47uF  [CAPC1608X87N]
C64  4.7uF  [CAPC2012X140N]
C65  4.7uF  [CAPC2012X140N]
D4  RCLAMP0531TQTCT  [DIONDFN2_100X60X43L25X50N]
D5  RCLAMP0531TQTCT  [DIONDFN2_100X60X43L25X50N]
D6  RCLAMP0531TQTCT  [DIONDFN2_100X60X43L25X50N]
F5  0154.125DR  [FUSM9750X381N]
F6  0154.125DR  [FUSM9750X381N]
J12  M80-8510842  [HARWIN_M80-851_8PIN]
J13  M80-8510842  [HARWIN_M80-851_8PIN]
J14  M80-8510642  [HARWIN_M80-851_6PIN]
J15  M80-8420342  [HARWIN_M80-842_3PIN]
Q1  SI2308BDS-T1-E3  [VISHAY_SOT-23]
Q2  SI2308BDS-T1-E3  [VISHAY_SOT-23]
Q3  SI2308BDS-T1-E3  [VISHAY_SOT-23]
Q4  SI2308BDS-T1-E3  [VISHAY_SOT-23]
Q5  SI2308BDS-T1-E3  [VISHAY_SOT-23]
Q6  SI2308BDS-T1-E3  [VISHAY_SOT-23]
R42  TBD  [MBARI_TBD0603_RESC]
R43  330  [RESC1608X50N]
R44  330  [RESC1608X50N]
R45  10.0K  [RESC1608X50N]
R46  0.05  [RESC3116X65N]
R47  2.00K  [RESC1608X50N]
R48  330  [RESC1608X50N]
R49  TBD  [MBARI_TBD0805_RESC]
R50  TBD  [MBARI_TBD0805_RESC]
R51  TBD  [MBARI_TBD0805_RESC]
R52  10.0K  [RESC1608X50N]
R53  0.05  [RESC3116X65N]
R54  TBD  [MBARI_TBD0805_RESC]
R55  100  [VISHAY_CRCW-0603_RESC]
R56  165.0K  [RESC1608X50N]
R57  2.00K  [RESC1608X50N]
R58  TBD  [MBARI_TBD0805_RESC]
R59  100  [VISHAY_CRCW-0603_RESC]
R60  165.0K  [RESC1608X50N]
R61  TBD  [MBARI_TBD0805_RESC]
R62  100  [VISHAY_CRCW-0603_RESC]
R63  165.0K  [RESC1608X50N]
R?#1  TBD  [MBARI_TBD0603_RESC]
SB6  0603  [MISC_JUMPER_SM0603]
SB7  0603  [MISC_JUMPER_SM0603]
SB8  0603  [MISC_JUMPER_SM0603]
SB9  0603  [MISC_JUMPER_SM0603]
U15  LT1910ES8#PBF  [SOIC127P599X175-8L86N]
U16  LT1910ES8#PBF  [SOIC127P599X175-8L86N]
sheet 7 I2C Devices
C66  0.10uF  [CAPC1608X87N]
C67  0.1uF  [MURATA_GCM188-0603_CAPC]
R64  14.0K  [RESC1608X50N]
R65  14.0K  [RESC1608X50N]
R66  14.0K  [RESC1608X50N]
U17  LTC4311CSC6#TRMPBF  [SOP65P210X100-6L20N]
U18  BME280  [BOSCH_BME280]
U19  24FC64FT-I/OT  [MICROCHIP_OT_5PIN]

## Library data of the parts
C1 C21 C29 = CAP: CAP CER 10UF 16V 20% X7R 0805; CLASS: DISCRETE; Dielectric Type: Capacitors; Manufacturer: Taiyo Yuden; Manufacturer PN: EMK212BB7106MG-T; PART_NUMBER: EMK212BB7106MG-T; Package Size: 0805 (2012 Metric); Rated Voltage: 16V; Temperature Coefficient: X7R; Tolerance: ±20%
C2 = CAP: CAP, CER, 0.10uF, 16V, 10%, X7R, 0603; CLASS: DISCRETE; Dielectric Type: Ceramic; Manufacturer: Kemet; Manufacturer PN: C0603C104K4RAC; PART_NUMBER: C0603C104K4RAC; Package Size: 0603; Rated Voltage: 16V; Temperature Coefficient: X7R; Tolerance: 10%
C3 C6 C9-C16 C34-C37 C45 C54-C60 C66 = CAP: CAP CER 0.1UF 25V 10% X7R 0603; CLASS: DISCRETE; Dielectric Type: Ceramic; Manufacturer: Kemet; Manufacturer PN: C0603C104K3RACTU; PART_NUMBER: C0603C104K3RAC; Package Size: 0603; Rated Voltage: 25V; Temperature Coefficient: X7R; Tolerance: 10%
C4 C5 = CAP: CAP CER 22PF 50V 5% NP0 0603; CLASS: DISCRETE; Dielectric Type: Capacitors; Manufacturer: Murata Electronics North America; Manufacturer PN: GRM1885C1H220JA01D; PART_NUMBER: GRM1885C1H220JA01D; Package Size: 0603 (1608 Metric); Rated Voltage: 50V; Temperature Coefficient: C0G, NP0; Tolerance: ±5%
C7 C8 = CAP: CAP CER 33PF 100V 1% NP0 0603; CLASS: DISCRETE; Dielectric Type: Capacitors; Manufacturer: AVX Corporation; Manufacturer PN: 06031A330FAT2A; PART_NUMBER: 06031A330FAT2A; Package Size: 0603 (1608 Metric); Rated Voltage: 100V; Temperature Coefficient: C0G, NP0; Tolerance: ±1%
JP1 = JUMPER_2PIN: MISC 2 PIN JUMPER 0.100" PITCH 0.025" SQ; CLASS: IO; PART_NUMBER: MISC_JMPR-TH-2PIN
R1 = RES: CLASS: DISCRETE; Manufacturer: Vishay; Manufacturer PN: CRCW06034K70JNEA; PART_NUMBER: CRCW06034K70JNEA; Package Size: 0603; Rated Power: 0.1W; Temperature Coefficient: 200ppm/K; Tolerance: 5%
R2 = RES: RES SMD 1K OHM 1% 1/10W 0603; CLASS: DISCRETE; Manufacturer: Vishay; Manufacturer PN: CRCW06031K00FKEA; PART_NUMBER: CRCW06031K00FKEA; Package Size: 0603; Rated Power: 0.1W; Temperature Coefficient: 100ppm/K; Tolerance: 1%
R3 = RES: RES 1.00M OHM 1/8W 1% 0805 SMD; CLASS: DISCRETE; Manufacturer: Vishay Dale; Manufacturer PN: CRCW08051M00FKEA; PART_NUMBER: CRCW08051M00FKEA; Package Size: 0805; Rated Power: 0.125W; Temperature Coefficient: 100ppm/K; Tolerance: 1%
SW1 = SW_SPST_12_34: SWITCH TACTILE SPST-NO 0.05A 12V; CLASS: DISCRETE; Manufacturer: TE Connectivity; Package Size: 6.00mm x 6.00mm
U1 = dsPIC33F_100TQFP: IC DSC 16BIT 256KB FLASH 100TQFP; CLASS: IC; Manufacturer: Microchip Technology; PART_NUMBER: DSPIC33FJ256MC710A-H/PF-ND; Package Size: 100-TQFP; Supply Voltage: 3 V - 3.6 V
U2 = REF19xx: IC VREF SERIES 3V SOT5; CLASS: IC; Manufacturer: Texas Instruments; Package Size: SOT-23-5 Thin, TSOT-23-5
Y1 = CRYSTAL: CRYSTAL 32.7680KHZ 12.5PF SMD; CLASS: DISCRETE; Frequency Tolerance: ±20ppm; Manufacturer: Epson Toyocom Corporation; Manufacturer PN: FC-135 32.7680KA-A3; PART_NUMBER: FC-135 32.7680KA-A3; Package Size: 2-SMD
Y2 = CRYSTAL: CRYSTAL 8.0000MHZ 18PF SMD; CLASS: DISCRETE; Frequency Stability: 30ppm; Frequency Tolerance: 30ppm; Manufacturer: TXC CORPORATION; Manufacturer PN: 7A-8.000MAAJ-T; PART_NUMBER: 7A-8.000MAAJ-T; Package Size: 0.197" L x 0.126" W (5.00mm x 3.20mm)
C17 C25 = CAP: CAP CER 47UF 10V 20% X7R 1210; CLASS: DISCRETE; Dielectric Type: Capacitors; Manufacturer: Taiyo Yuden; Manufacturer PN: LMK325B7476MM-TR; PART_NUMBER: LMK325B7476MM-TR; Package Size: 1210 (3225 Metric); Rated Voltage: 10V; Temperature Coefficient: X7R; Tolerance: ±20%
C18 C19 C26 C27 = CAP: CAP CER 0.1UF 50V X7R 0508; CLASS: DISCRETE; Dielectric Type: Capacitors; Manufacturer: AVX Corporation; Manufacturer PN: 05085C104KAJ2A; PART_NUMBER: 05085C104KAJ2A; Package Size: 0508 (1220 Metric); Rated Voltage: 50V; TMP Manufacturer: AVX Corp; TMP Manufacturer PN: 0508YC104KAT2V; Temperature Coefficient: X7R; Tolerance: 10%
C20 C28 = CAP: CAP CER 1UF 50V X7R 1206; CLASS: DISCRETE; Manufacturer: Murata Electronics North America; Manufacturer PN: GCM31MR71H105KA55L; PART_NUMBER: GCM31MR71H105KA55L; Package Size: 1206 (3216 Metric); Rated Voltage: 50V; Temperature Coefficient: X7R; Tolerance: 10%
C22 C30 = CAP: CLASS: DISCRETE; Dielectric Type: Ceramic; Manufacturer: Kemet; Manufacturer PN: C0603C104K5RAC; PART_NUMBER: C0603C104K5RAC; Package Size: 0603; Rated Voltage: 50V; Temperature Coefficient: X7R; Tolerance: 10%
C23 C31 = CAP: CLASS: DISCRETE; Dielectric Type: Ceramic; Manufacturer: Kemet; Manufacturer PN: C0805C102K4RAC; PART_NUMBER: C0805C102K4RAC; Package Size: 0805; Rated Voltage: 16V; Temperature Coefficient: X7R; Tolerance: 10%
C24 C32 C67 = CAP: CAP CER 0.1UF 50V X7R 0603; CLASS: DISCRETE; Manufacturer: Murata Electronics North America; Manufacturer PN: GCM188R71H104KA57J; PART_NUMBER: GCM188R71H104KA57J; Package Size: 0603 (1608 Metric); Rated Voltage: 50V; Temperature Coefficient: X7R; Tolerance: 10%
C33 = CAP: CAP FILM 10000PF 20% 1KVDC RAD; CLASS: DISCRETE; Dielectric Type: Polypropylene (PP), Metallized; Manufacturer: Vishay BC Components; Manufacturer PN: BFC233860103; PART_NUMBER: BFC233860103; Package Size: Radial; Tolerance: 20%
J1 = CON2: CONN HDR 2MM R/A W/LATCH 2POS; CLASS: IO; Manufacturer: Harwin Inc
JR1 JR2 = RES_3PIN-JMPR: 0603 3PIN JUMPER; CLASS: DISCRETE; PART_NUMBER: SM_0603-3P-JMPR; Package Size: 0603
R4 R7 = RES: CLASS: DISCRETE; Manufacturer: Vishay; Manufacturer PN: CRCW080520K0FKEA; PART_NUMBER: CRCW080520K0FKEA; Package Size: 0805; Rated Power: 0.125W; Temperature Coefficient: 100ppm/K; Tolerance: 1%
R5 = RES: CLASS: DISCRETE; Manufacturer: Vishay; Manufacturer PN: CRCW060371K5FKEA; PART_NUMBER: CRCW060371K5FKEA; Package Size: 0603; Rated Power: 0.1W; Temperature Coefficient: 100ppm/K; Tolerance: 1%
R6 R9 = RES: CLASS: DISCRETE; Manufacturer: Vishay; Manufacturer PN: CRCW060333K2FKEA; PART_NUMBER: CRCW060333K2FKEA; Package Size: 0603; Rated Power: 0.1W; Temperature Coefficient: 100ppm/K; Tolerance: 1%
R8 = RES: CLASS: DISCRETE; Manufacturer: Vishay; Manufacturer PN: CRCW060343K2FKEA; PART_NUMBER: CRCW060343K2FKEA; Package Size: 0603; Rated Power: 0.1W; Temperature Coefficient: 100ppm/K; Tolerance: 1%
ST1 = SCREW-TERMINAL: #4 SCREW TERMINAL, PANHEAD; CLASS: DISCRETE; PART_NUMBER: MNT4_PANHEAD
TP1-TP4 = TESTPOINT: PC TEST POINT MINIATURE SMT; CLASS: DISCRETE; Manufacturer: Keystone Electronics; Package Size: 2.67 x 1.02 mm
TP5 = TESTPOINT: TEST POINT PC MINI .040"D RED; CLASS: DISCRETE; Manufacturer: Keystone Electronics; Manufacturer PN: 5000; PART_NUMBER: 5000; Package Size: 2.50 Dia
TP6 = TESTPOINT: TEST POINT PC MINI .040"D BLACK; CLASS: DISCRETE; Manufacturer: Keystone Electronics; Manufacturer PN: 5001; PART_NUMBER: 5001; Package Size: 2.50 Dia
U3 U5 = LTM8063: DC DC CONVERTER 0.8-15V; CLASS: IC; Manufacturer: Linear Technology/Analog Devices; Package Size: 28-FBGA Module
U4 = ADM7171: IC REG LDO 3.3V 1A 8-LFCSP; CLASS: IC; Manufacturer: Analog Devices Inc; Package Size: 8-WFDFN Exposed Pad, CSP
U6 = ADM7171: IC REG LDO 5V 1A 8-LFCSP; CLASS: IC; Manufacturer: Analog Devices Inc; Package Size: 8-WFDFN Exposed Pad, CSP
D1 D2 = DIODE_TVS_BI_DIR: TVS DIODE 30V 48.4V DO214AA; CLASS: DISCRETE; Manufacturer: Littelfuse Inc.; Package Size: DO-214AA, SMB; Rated Power: 600W
D3 = WURTH_824011: TVS DIODE 5VWM 8.5VC SOT23; CLASS: DISCRETE; Manufacturer: Wurth Electronics Inc; Package Size: SC-74A, SOT-753
J2 J5 J11 J14 = CON6: CONN HDR 2MM R/A W/LATCH 6POS; CLASS: IO; Manufacturer: Harwin Inc
J3 = CON3: CONN, RT Angle Header, --, 3, TH; CLASS: IO; Contact Voltage: 250 V; Manufacturer: Molex Inc; Package Size: 13.59 x 10.17 mm
J4 J10 = CON4: CONN HDR 2MM R/A W/LATCH 4POS; CLASS: IO; Manufacturer: Harwin Inc
J6 = HEADER_8X2: CONN HEADER DUAL ROW 16POS .100 STR 30AU; CLASS: IO; Manufacturer: FCI; PART_NUMBER: 68602-116HLF_SYM-MOD1; Package Size: 0.230" (5.84mm)
L1 = IND_CHOKE_2LINE-ARRAY_12_43_NP: CMC 51UH 200MA 2LN SMD AEC-Q200; CLASS: DISCRETE; Manufacturer: TDK Corporation; Package Size: Horizontal, 4 PC Pad
R10 = RES: CLASS: DISCRETE; Manufacturer: Vishay; Manufacturer PN: CRCW060356K2FKEA; PART_NUMBER: CRCW060356K2FKEA; Package Size: 0603; Rated Power: 0.1W; Temperature Coefficient: 100ppm/K; Tolerance: 1%
R11 = RES: CLASS: DISCRETE; Manufacturer: Vishay; Manufacturer PN: CRCW0805100RFKEA; PART_NUMBER: CRCW0805100RFKEA; Package Size: 0805; Rated Power: 0.125W; Temperature Coefficient: 100ppm/K; Tolerance: 1%
R12 = RES: CLASS: DISCRETE; Manufacturer: Vishay; Manufacturer PN: CRCW060313K0FKEA; PART_NUMBER: CRCW060313K0FKEA; Package Size: 0603; Rated Power: 0.1W; Temperature Coefficient: 100ppm/K; Tolerance: 1%
R13 R14 = RES: CLASS: DISCRETE; Manufacturer: Vishay; Manufacturer PN: CRCW120660R4FKEA; PART_NUMBER: CRCW120660R4FKEA; Package Size: 1206; Rated Power: 0.25W; Temperature Coefficient: 100ppm/K; Tolerance: 1%
R15 = RES: CLASS: DISCRETE; Manufacturer: Vishay; Manufacturer PN: CRCW060310K5FKEA; PART_NUMBER: CRCW060310K5FKEA; Package Size: 0603; Rated Power: 0.1W; Temperature Coefficient: 100ppm/K; Tolerance: 1%
SB1-SB9 = SB_JUMPER: MISC 2 PIN JUMPER SOLDER BRIDGE 0603; CLASS: IO; PART_NUMBER: MISC_SOLDERBRIDGE_SM0603
TS1 TS2 = DIODE_TVS_ARRAY_SRV05-4: TVS DIODE 5V 4CH BI SOT23-6; CLASS: DISCRETE; Manufacturer: Semtech; Package Size: SOT-23-6; Rated Power: 300W; Rated Voltage: 6V
U7 = LTM2889: DGTL ISO 2.5KV 2CH CAN 32BGA; CLASS: IC; Manufacturer: Linear Technology/Analog Devices; Package Size: 32-BBGA; Supply Voltage: 3 V - 3.6 V
U8 = MAX3471xUA: IC TXRX DIFF RS485/422 8-UMAX; CLASS: IC; Manufacturer: Maxim Integrated Products; Package Size: 8-TSSOP, 8-MSOP (0.118", 3.00mm Width); Supply Voltage: 2.5 V ~ 5.5 V
U9 = MAX3233E: IC TXRX RS232 DUAL250KBPS 20SOIC; CLASS: IC; Manufacturer: Maxim Integrated Products; PART_NUMBER: MAX3233EEWP_G36; Package Size: 20-SOIC (0.295", 7.50mm Width); Supply Voltage: 3 V ~ 3.6 V
C38 C39 C42 C46-C48 = CAP: CAP FILM 10000PF 2% 16VDC 0805; CLASS: DISCRETE; Dielectric Type: Polyphenylene Sulfide (PPS), Metallized - Stacked; Manufacturer: Panasonic Electronic Components; Manufacturer PN: ECH-U1C103GX5; PART_NUMBER: ECH-U1C103GX5; Package Size: 0805 (2012 Metric); Tolerance: 2%
C40 C49 = CAP: CAP CER 680PF 100V 5% NP0 0805; CLASS: DISCRETE; Dielectric Type: Capacitors; Manufacturer: Kemet; Manufacturer PN: C0805C681J1GACTU; PART_NUMBER: C0805C681J1GACTU; Package Size: 0805 (2012 Metric); Rated Voltage: 100V; Temperature Coefficient: C0G, NP0; Tolerance: ±5%
C41 C50 = CAP: CAP CER 560PF 50V 10% X7R 0603; CLASS: DISCRETE; Dielectric Type: Capacitors; Manufacturer: Murata Electronics North America; Manufacturer PN: GRM188R71H561KA01D; PART_NUMBER: GRM188R71H561KA01D; Package Size: 0603 (1608 Metric); Rated Voltage: 50V; Temperature Coefficient: X7R; Tolerance: ±10%
C43 C44 C51 C52 = CAP: CAP CER 6800PF 50V 10% X7R 0805; CLASS: DISCRETE; Dielectric Type: Capacitors; Manufacturer: Yageo; Manufacturer PN: CC0805KRX7R9BB682; PART_NUMBER: CC0805KRX7R9BB682; Package Size: 0805 (2012 Metric); Rated Voltage: 50V; Temperature Coefficient: X7R; Tolerance: 10%
C53 = CAP: CAP CER 0.1UF 50V 5% X7R 0805; CLASS: DISCRETE; Dielectric Type: Capacitors; Manufacturer: AVX Corporation; Manufacturer PN: 08055C104JAT2A; PART_NUMBER: 08055C104JAT2A; Package Size: 0805 (2012 Metric); Rated Voltage: 50V; Temperature Coefficient: X7R; Tolerance: ±5%
J7 J12 J13 = CON8: CONN HDR 2MM R/A W/LATCH 8POS; CLASS: IO; Manufacturer: Harwin Inc
R16 R21 = RES_ARRAY_2: Resistor Networks & Arrays 10K/10Kohm .1%/.05% 10/5ppm 0606 Auto; CLASS: DISCRETE; Manufacturer: Vishay / Beyschlag; Manufacturer PN: ACASN1002U1002P1AT; PART_NUMBER: ACASN1002U1002P1AT; Package Size: 0606 (1616 metric); Temperature Coefficient: 10 PPM / C; Tolerance: 0.1%
R17 R22 = RES: CLASS: DISCRETE; Manufacturer: Vishay; Manufacturer PN: CRCW08055K62FKEA; PART_NUMBER: CRCW08055K62FKEA; Package Size: 0805; Rated Power: 0.125W; Temperature Coefficient: 100ppm/K; Tolerance: 1%
R18 R23 = RES: CLASS: DISCRETE; Manufacturer: Vishay; Manufacturer PN: CRCW0805160KJNEA; PART_NUMBER: CRCW0805160KJNEA; Package Size: 0805; Rated Power: 0.125W; Temperature Coefficient: 200ppm/K; Tolerance: 5%
R19 R20 R24 R25 = RES: CLASS: DISCRETE; Manufacturer: Vishay; Manufacturer PN: CRCW080533K2FKEA; PART_NUMBER: CRCW080533K2FKEA; Package Size: 0805; Rated Power: 0.125W; Temperature Coefficient: 100ppm/K; Tolerance: 1%
R26 = RES: CLASS: DISCRETE; Manufacturer: Vishay; Manufacturer PN: CRCW060354K9FKEA; PART_NUMBER: CRCW060354K9FKEA; Package Size: 0603; Rated Power: 0.1W; Temperature Coefficient: 100ppm/K; Tolerance: 1%
RN1 RN2 = RES_ARRAY_4: RES ARRAY 4 RES MULT OHM 1206; CLASS: DISCRETE; Manufacturer: Vishay Beyschlag; Manufacturer PN: ACASA1002E3002P100; PART_NUMBER: ACASA1002E3002P100; Package Size: 1206 (3216 Metric), Convex, Long Side Terminals; Temperature Coefficient: 25ppm/C; Tolerance: 0.25%
U10 = LTC2055_MS8: IC OPAMP CHOPPER 500KHZ 8MSOP; CLASS: IC; Manufacturer: Linear Technology; Package Size: 8-TSSOP, 8-MSOP (0.118", 3.00mm Width); PartGroup: RED; Supply Voltage: 2.7 V - 11 V, 1.35 V - 5.5 V
U11-U14 = LTC2055_MS8: IC OPAMP CHOPPER 500KHZ 8MSOP; CLASS: IC; Manufacturer: Linear Technology; Package Size: 8-TSSOP, 8-MSOP (0.118", 3.00mm Width); Supply Voltage: 2.7 V - 11 V, 1.35 V - 5.5 V
DN1-DN4 = DIODE_DUAL_ACJ: DIODE SCHOTTKY DUAL 30V SOT323; CLASS: DISCRETE; Manufacturer: ON Semiconductor; Package Size: SC-70, SOT-323; Rated Voltage: 800mV @ 100mA
F1-F6 = FUSEHOLDER_2T_2PIN: FUSEBLOCK W/.125A FUSE SMD FST; CLASS: DISCRETE; Manufacturer: Littelfuse Inc; Package Size: SMD w/Holder
J8 J9 J15 = CON3: CONN HDR 2MM R/A W/LATCH 3POS; CLASS: IO; Manufacturer: Harwin Inc
R27 R31 R42 R?#1 = RES: TO BE DETERMINED, HEIGHT 0.022"; CLASS: DISCRETE; PART_NUMBER: TBD_R0603; Package Size: 0603
R28 R32 R45 R52 = RES: RES SMD 10K OHM 1% 1/10W 0603; CLASS: DISCRETE; Manufacturer: Vishay; Manufacturer PN: CRCW060310K0FKEA; PART_NUMBER: CRCW060310K0FKEA; Package Size: 0603; Rated Power: 0.1W; Temperature Coefficient: 100ppm/K; Tolerance: 1%
R29 R33 R35 R38 = RES: CLASS: DISCRETE; Manufacturer: Vishay; Manufacturer PN: CRCW060316K2FKEA; PART_NUMBER: CRCW060316K2FKEA; Package Size: 0603; Rated Power: 0.1W; Temperature Coefficient: 100ppm/K; Tolerance: 1%
R30 R34 = RES: CLASS: DISCRETE; Manufacturer: Vishay; Manufacturer PN: CRCW06034K22FKEA; PART_NUMBER: CRCW06034K22FKEA; Package Size: 0603; Rated Power: 0.1W; Temperature Coefficient: 100ppm/K; Tolerance: 1%
R36 R41 = RES: CLASS: DISCRETE; Manufacturer: Vishay; Manufacturer PN: CRCW0603147RFKEA; PART_NUMBER: CRCW0603147RFKEA; Package Size: 0603; Rated Power: 0.1W; Temperature Coefficient: 100ppm/K; Tolerance: 1%
R37 R40 = RES: RES 0.0 OHM 1/8W JUMP 0805 SMD; CLASS: DISCRETE; Manufacturer: Vishay Dale; Manufacturer PN: CRCW08050000Z0EA; PART_NUMBER: CRCW08050000Z0EA; Package Size: 0805 (2012 Metric); Rated Power: 0.125W, 1/8W; Tolerance: Jumper
C61-C63 = CAP: CAP CER 0.47UF 16V X7R 0603; CLASS: DISCRETE; Dielectric Type: Ceramic; Manufacturer: Kemet; Manufacturer PN: C0603C474K4RAC; PART_NUMBER: C0603C474K4RAC; Package Size: 0603; Rated Voltage: 16V; Temperature Coefficient: X7R; Tolerance: 10%
C64 C65 = CAP: CAP CER 4.7UF 6.3V 10% X7R 0805; CLASS: DISCRETE; Dielectric Type: Capacitors; Manufacturer: Kemet; Manufacturer PN: C0805C475K9RACTU; PART_NUMBER: C0805C475K9RACTU; Package Size: 0805 (2012 Metric); Rated Voltage: 6.3V; Temperature Coefficient: X7R; Tolerance: 10%
D4-D6 = DIODE_TVS_BI_DIR: TVS DIODE 5V 20V SLP1006P2T; CLASS: DISCRETE; Manufacturer: Semtech Corporation; Package Size: 0402 (1006 Metric)
Q1-Q6 = MOSFET_I_EN_GSD: MOSFET N-CH 60V 2.3A SOT23-3; CLASS: DISCRETE; Manufacturer: Vishay Siliconix; Package Size: TO-236-3, SC-59, SOT-23-3; Polarity: N-Channel
R43 R44 R48 = RES: RES SMD 330 OHM 5% 1/10W 0603; CLASS: DISCRETE; Manufacturer: Vishay; Manufacturer PN: CRCW0603330RJNEA; PART_NUMBER: CRCW0603330RJNEA; Package Size: 0603; Rated Power: 0.1W; Temperature Coefficient: 200ppm/K; Tolerance: 5%
R46 R53 = RES: RES .05 OHM 1/2W 1% 1206 SMD; CLASS: DISCRETE; Manufacturer: Stackpole Electronics Inc; Manufacturer PN: CSR1206FK50L0; PART_NUMBER: CSR1206FK50L0; Package Size: 1206 (3216 Metric); Rated Power: 0.5W, 1/2W; Temperature Coefficient: ±100ppm/°C; Tolerance: ±1%
R47 R57 = RES: CLASS: DISCRETE; Manufacturer: Vishay; Manufacturer PN: CRCW06032K00FKEA; PART_NUMBER: CRCW06032K00FKEA; Package Size: 0603; Rated Power: 0.1W; Temperature Coefficient: 100ppm/K; Tolerance: 1%
R49-R51 R54 R58 R61 = RES: TO BE DETERMINED, HEIGHT 0.028"; CLASS: DISCRETE; PART_NUMBER: TBD_R0805; Package Size: 0805
R55 R59 R62 = RES: RES SMD 100 OHM 1% 1/10W 0603; CLASS: DISCRETE; Manufacturer: Vishay; Manufacturer PN: CRCW0603100RFKEA; PART_NUMBER: CRCW0603100RFKEA; Package Size: 0603; Rated Power: 0.1W; Temperature Coefficient: 100ppm/K; Tolerance: 1%
R56 R60 R63 = RES: CLASS: DISCRETE; Manufacturer: Vishay; Manufacturer PN: CRCW0603165KFKEA; PART_NUMBER: CRCW0603165KFKEA; Package Size: 0603; Rated Power: 0.1W; Temperature Coefficient: 100ppm/K; Tolerance: 1%
U15 U16 = LT1910: IC MOSFET DRIVER HIGH-SIDE 8SOIC; CLASS: DISCRETE; Manufacturer: Linear Technology; Package Size: 8-SOIC (0.154", 3.90mm Width)
R64-R66 = RES: CLASS: DISCRETE; Manufacturer: Vishay; Manufacturer PN: CRCW060314K0FKEA; PART_NUMBER: CRCW060314K0FKEA; Package Size: 0603; Rated Power: 0.1W; Temperature Coefficient: 100ppm/K; Tolerance: 1%
U17 = LTC4311_SC6: IC ACCELERATOR SMBUS DL SC70-6; CLASS: IC; Manufacturer: Linear Technology; Package Size: 6-TSSOP, SC-88, SOT-363; Supply Voltage: 1.6 V ~ 5.5 V
U18 = BME280: SENSOR PRESSURE HUMIDITY TEMP; CLASS: IC; Manufacturer: Bosch Sensortec; Package Size: 8-VFLGA; Supply Voltage: 1.71 V - 3.6 V
U19 = 24FC64_OT: IC EEPROM 64K I2C 1MHZ SOT23-5; CLASS: IC; Manufacturer: Microchip Technology; Package Size: SC-74A, SOT-753; Supply Voltage: 1.7 V - 5.5 V

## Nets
3.3V: C6.1 C9.1 C10.1 C11.1 C12.1 C13.1 C14.1 C15.1 C16.1 C21.1 C34.1 C35.1 C36.1 C37.1 C45.1 C53.1 C54.1 C56.1 C59.1 C66.1 C67.1 D3.5(VDD) DN1.2(C) DN2.2(C) DN3.2(C) DN4.2(C) F5.2 J2.2 J6.6 J7.8 R1.1 R45.1 R52.1 R64.1 R65.1 R66.1 SB8.2 TP2.1(TP) TS1.5 TS2.5 U1.2(VDD) U1.16(VDD) U1.30(AVDD) U1.37(VDD) U1.46(VDD) U1.62(VDD) U1.86(VDD) U2.3(EN) U2.4(Vin) U4.1(VOUT1) U4.2(VOUT2) U4.3(SNS) U7.A6(VL) U7.A7(VCC) U7.A8(PVCC) U7.B7(VCC) U7.B8(PVCC) U8.8(Vcc) U9.9(Vcc) U9.10(\\~{FORCEOFF}) U10.8(V+) U11.8(V+) U12.8(V+) U13.8(V+) U14.8(V+) U17.1(VCC) U17.3(EN) U18.2(CSB) U18.6(VDDIO) U18.8(VDD) U19.4(VCC)
5V: C29.1 J6.4 TP4.1(TP) U6.1(VOUT1) U6.2(VOUT2) U6.3(SNS)
15V: C19.1 C20.1 C27.1 C28.1 F1.2 F2.2 F3.2 J1.1 J6.2 J7.6 J15.3 JR1.1 JR2.1 R53.1 SB6.2 SB9.2 TP5.1(TP) U3.B3(RUN) U3.B4(VINB4) U3.C4(VINC4) U5.B3(RUN) U5.B4(VINB4) U5.C4(VINC4) U16.8(V+)
GND_CAN: D1.2(A2) D2.2(A2) J3.3 R10.2 R12.1 R15.1 U7.K1(GND2) U7.K2(GND2) U7.K3(GND2) U7.K4(GND2) U7.K6(GND2) U7.K7(GND2) U7.K8(GND2) U7.L4(GND2)
GND_EARTH: C33.1 ST1.1
GND_SIGNAL: C1.2 C2.2 C3.2 C4.2 C5.2 C6.2 C7.2 C8.2 C9.2 C10.2 C11.2 C12.2 C13.2 C14.2 C15.2 C16.2 C17.2 C18.2 C19.2 C20.2 C21.2 C22.2 C23.2 C24.2 C25.2 C26.2 C27.2 C28.2 C29.2 C30.2 C31.2 C32.2 C33.2 C34.2 C35.2 C36.2 C37.2 C38.1 C40.2 C41.2 C42.2 C45.2 C46.1 C48.2 C49.2 C50.2 C53.2 C54.2 C55.2 C56.2 C57.2 C58.2 C59.2 C60.2 C61.2 C62.2 C63.2 C64.2 C65.2 C66.2 C67.2 D3.2(GND) D4.1(A1) D5.1(A1) D6.1(A1) DN1.1(A) DN2.1(A) DN3.1(A) DN4.1(A) J1.2 J2.3 J4.4 J5.5 J6.12 J6.14 J6.16 J7.5 J7.7 J8.3 J9.3 J10.4 J11.4 J11.5 J12.7 J12.8 J13.8 J15.2 JR1.3 JR2.3 Q1.2(S) Q3.2(S) Q5.2(S) Q6.2(S) R5.2 R6.2 R8.2 R9.2 R26.2 R30.1 R34.1 R37.2 R40.2 R56.2 R60.2 R63.2 RN1.2 RN2.2 SB4.2 SW1.1 SW1.2 TP6.1(TP) TS1.2 TS2.2 U1.15(VSS) U1.28(VREF-/RA9) U1.31(AVSS) U1.36(VSS) U1.45(VSS) U1.65(VSS) U1.75(VSS) U2.2(GND) U3.A1(GNDA1) U3.A4(GNDA4) U3.C2(GNDC2) U3.C3(GNDC3) U3.D1(GNDD1) U3.D2(GNDD2) U3.D3(GNDD3) U3.D4(GNDD4) U3.E1(GNDE1) U3.E2(GNDE2) U3.E3(GNDE3) U3.E4(GNDE4) U4.6(GND) U4.9(GND) U5.A1(GNDA1) U5.A4(GNDA4) U5.C2(GNDC2) U5.C3(GNDC3) U5.D1(GNDD1) U5.D2(GNDD2) U5.D3(GNDD3) U5.D4(GNDD4) U5.E1(GNDE1) U5.E2(GNDE2) U5.E3(GNDE3) U5.E4(GNDE4) U6.6(GND) U6.9(GND) U7.A1(\\~{R}E) U7.B1(GND) U7.B2(GND) U7.B3(GND) U7.B4(GND) U7.B5(GND) U7.B6(GND) U8.5(GND) U9.5(FORCEON) U9.18(Gnd) U10.4(V-) U11.4(V-) U12.4(V-) U13.4(V-) U14.4(V-) U15.1(GND) U16.1(GND) U17.2(GND2) U17.5(GND5) U18.1(GND) U18.5(SDO/ADDR) U18.7(GND) U19.2(VSS)
AN0: U1.25(PGED3/AN0/CN2/RB0) U14.1(OutA) U14.2(INA-)
AN1: U1.24(PGEC3/AN1/CN3/RB1) U14.6(INB-) U14.7(OutB)
AN10: U1.34(AN10/RB10) U13.6(INB-) U13.7(OutB)
AN11: U1.35(AN11/RB11) U13.1(OutA) U13.2(INA-)
AN16: C44.2 U1.6(AN16/T2CK/T7CK/RC1) U11.6(INB-) U11.7(OutB)
AN17: C52.2 U1.7(AN17/T3CK/T6CK/RC2) U12.6(INB-) U12.7(OutB)
ASIG_CH1+: J7.1 R16.1(1R1)
ASIG_CH1-: J7.2 R16.2(1R2)
ASIG_CH2+: J7.3 R21.1(1R1) SB3.1
ASIG_CH2-: J7.4 R21.2(1R2) SB4.1
CAN1_RX: U1.87(C1RX/RF0) U7.A2(RXD)
CAN1_TX: U1.88(C1TX/RF1) U7.A3(TXD)
CANH: D1.1(A1) J3.1 L1.4 R13.1
CANL: D2.1(A1) J3.2 L1.3 R14.2
D1+: J14.1 R49.2
D1-: J14.4 R54.1
D2+: J14.2 R50.2
D2-: J14.5 R58.1
D3+: J14.3 R51.2
D3-: J14.6 R61.1
DIO0: J12.4 R43.1
DIO1: J12.5 R44.1
DIO2: J12.6 R48.1
I2C1_EEPROM_WP: R66.2 U1.58(SCL2/RA2) U19.5(WP)
I2C1_SCL: D3.3(IO1) J6.8 R64.2 U1.57(SCL1/RG2) U17.4(BUS2) U18.4(SCK) U19.1(SCL)
I2C1_SDA: D3.4(IO2) J6.10 R65.2 U1.56(SDA1/RG3) U17.6(BUS1) U18.3(SDI/SDA) U19.3(SDA)
LASERRNGPWR_15V_INPUT: J11.6 SB7.2
LASERRNGPWR_15V_SWITCHED: F4.2 Q2.2(S)
MCLR: R2.2 R11.1 U1.13(~{MCLR})
OSC1: C7.1 R3.2 U1.63(OSC1/CLKIN/RC12) Y2.1
OSC2: C8.1 R3.1 U1.64(OSC2/CLKO/RC15) Y2.2
PSIGA_10V: J8.2 R28.1
PSIGB_10V: J9.2 R32.1
PWM1H: J13.1 U1.94(PWM1H/RE1)
PWM1L: J13.2 U1.93(PWM1L/RE0)
PWM2H: J13.3 U1.99(PWM2H/RE3)
PWM2L: J13.4 U1.98(PWM2L/RE2)
PWM3H: J13.5 U1.3(PWM3H/RE5)
PWM3L: J13.6 U1.100(PWM3L/RE4)
PWM4L: J13.7 U1.4(PWM4L/RE6)
RB3_UM_EN: Q1.1(G) U1.22(AN3/INDX/CN5/RB3)
RB6_PGEC1: J2.5 U1.26(PGEC1/AN6/OCFA/RB6)
RB7_PGED1: J2.4 U1.27(PGED1/AN7/RB7)
RD2_GASBYPASS_EN: R59.2 U1.77(OC3/RD2)
RD3_STEPPER_ENABLE: R55.2 U1.78(OC4/RD3)
RD4: C61.1 D4.2(A2) R43.2 U1.81(OC5/CN13/RD4)
RD5: C62.1 D5.2(A2) R44.2 U1.82(OC6/CN14/RD5)
RD6: C63.1 D6.2(A2) R48.2 U1.83(OC7/CN15/RD6)
RD7: R62.2 U1.84(OC8/UPDN/CN16/RD7)
RD12_LRF_EN: R47.1 U1.79(IC5/RD12) U15.4(IN)
RD13_NFAULT_LRFPOW: R45.2 U1.80(IC6/CN19/RD13) U15.3(~{FAULT})
RF12: U1.40(~{U2CTS}/RF12) U8.2(~{RE})
RF13: U1.39(~{U2RTS}/RF13) U8.3(DE)
RG0_CAN1_SILENT: U1.90(C2RX/RG0) U7.A4(S)
RG1_CAN1_ENABLE: U1.89(C2TX/RG1) U7.A5(ON)
RG14_SW1_NFLT: R52.2 U1.95(RG14) U16.3(~{FAULT})
RG15_SW1_EN: R57.1 U1.1(RG15) U16.4(IN)
RS232_CTS: J5.4 U9.20(R2IN)
RS232_RTS: J5.2 U9.19(T2OUT)
RS232_RXD: J5.3 U9.8(R1IN)
RS232_TXD: J5.1 U9.7(T1OUT)
RS485_A: J4.2 SB2.1 U8.6(A)
RS485_B: J4.1 SB1.1 U8.7(B)
SOSCI: C5.1 U1.73(PGED2/SOSCI/CN1/RC13) Y1.2
SOSCO: C4.1 U1.74(PGEC2/SOSCO/T1CK/CN0/RC14) Y1.1
SPI1_MISO: J6.13 TS2.6 U1.54(SDI1/RF7)
SPI1_MOSI: J6.11 TS2.1 U1.53(SDO1/RF8)
SPI1_SCLK: J6.9 TS2.3 U1.55(SCK1/INT0/RF6)
SPI1_SS: J6.15 TS2.4 U1.23(AN2/~{SS1}/CN4/RB2)
SPI2_MISO: J6.5 TS1.6 U1.11(SDI2/CN9/RG7)
SPI2_MOSI: J6.3 TS1.1 U1.12(SDO2/CN10/RG8)
SPI2_SCLK: J6.1 TS1.3 U1.10(SCK2/CN8/RG6)
SPI2_SS: J6.7 TS1.4 U1.14(~{SS2}/CN11/RG9)
U1CTS: U1.47(IC7/~{U1CTS}/CN20/RD14) U9.1(R2OUT)
U1RTS: U1.48(IC8/~{U1RTS}/CN21/RD15) U9.3(T2IN)
U1RXD: U1.52(U1RX/RF2) U9.6(R1OUT)
U1TXD: U1.51(U1TX/RF3) U9.4(T1IN)
U2RXD: SB1.2 U1.49(U2RX/CN17/RF4) U8.1(RO)
U2TXD: SB2.2 U1.50(U2TX/CN18/RF5) U8.4(DI)
UM_IN+: J12.2 R42.1
UM_IN-: J12.3 R?#1.1
N08765: C1.1 C2.1 U1.85(VCAP)
N14987: JP1.1 R1.2 R2.1 SW1.3 SW1.4
N38405: C3.1 JP1.2
N39747: U1.29(VREF+/RA10) U2.5(Vref)
N47726: J2.1 R11.2
N72482: C57.1 DN2.3(J) R33.2 U13.5(INB+)
N72600: R27.2 R28.2 R29.1 R30.2
N72690: C55.1 DN1.3(J) R29.2 U13.3(INA+)
N72804: R31.2 R32.2 R33.1 R34.2
N72852: F2.1 J9.1 R31.1
N75830: F1.1 J8.1 R27.1
N76571: F3.1 J10.1
N76619: J10.2 R35.2 R36.1
N76675: J10.3 R36.2 R37.1
N76787: C58.1 DN3.3(J) R35.1 U14.3(INA+)
N77226: F4.1 J11.1
N77274: J11.2 R38.2 R41.1
N77330: J11.3 R40.1 R41.2
N77442: C60.1 DN4.3(J) R38.1 U14.5(INB+)
N78880: C43.2 R19.1 U11.1(OutA) U11.2(INA-)
N79426: C43.1 R17.2 R18.1
N79442: C40.1 R18.2 U11.3(INA+)
N79600: C44.1 R19.2 R20.1
N79616: C41.1 R20.2 U11.5(INB+)
N83438: C51.2 R24.1 U12.1(OutA) U12.2(INA-)
N83538: C51.1 R22.2 R23.1 R26.1
N83554: C49.1 R23.2 U12.3(INA+)
N83666: C52.1 R24.2 R25.1
N83682: C50.1 R25.2 U12.5(INB+)
N87637: F5.1 J12.1 R42.2
N98820: Q2.1(G) U15.5(GATE)
N98894: Q2.3(D) R46.2 U15.6(SENSE)
N98912: R46.1 SB6.1 SB7.1 U15.8(V+)
N99153: C64.1 R47.2 U15.2(TIMER)
N140572: F6.2 Q4.2(S)
N140988: Q4.1(G) U16.5(GATE)
N141012: Q4.3(D) R53.2 U16.6(SENSE)
N141056: C65.1 R57.2 U16.2(TIMER)
N306497: F6.1 J15.1
N326359: L1.1 U7.L3(CANH)
N326376: L1.2 U7.L1(CANL)
N326647: R15.2 U7.L5(RS)
N327074: R10.1 U7.L7(VCC2) U7.L8(VCC2)
N327081: R12.2 U7.L6(ADJ)
N348444: Q5.1(G) R59.1 R60.1
N352220: Q3.1(G) R55.1 R56.1
N352274: Q6.1(G) R62.1 R63.1
N352849: Q3.3(D) R54.2
N352881: Q5.3(D) R58.2
N352913: Q6.3(D) R61.2
N375304: R49.1 R50.1 R51.1 SB8.1 SB9.1
N3545511: R13.2 R14.1 U7.L2(SPLIT+)
N3873829: C17.1 C18.1 R4.1 TP1.1(TP) U3.F1(VOUTF1) U3.F2(VOUTF2) U3.F3(VOUTF3) U3.F4(VOUTF4) U3.G1(VOUTG1) U3.G2(VOUTG2) U3.G3(VOUTG3) U3.G4(VOUTG4) U4.7(VIN1) U4.8(VIN2)
N3874187: C22.1 R4.2 U3.B1(PG) U4.5(EN)
N3874207: JR1.2 U3.B2(SYNC)
N3874227: C23.1 U4.4(SS)
N3874259: C24.1 U3.A3(TR/SS)
N3874331: R6.1 U3.C1(RT)
N3874339: R5.1 U3.A2(FB)
N3874673: C25.1 C26.1 R7.1 TP3.1(TP) U5.F1(VOUTF1) U5.F2(VOUTF2) U5.F3(VOUTF3) U5.F4(VOUTF4) U5.G1(VOUTG1) U5.G2(VOUTG2) U5.G3(VOUTG3) U5.G4(VOUTG4) U6.7(VIN1) U6.8(VIN2)
N3875031: C30.1 R7.2 U5.B1(PG) U6.5(EN)
N3875051: JR2.2 U5.B2(SYNC)
N3875071: C31.1 U6.4(SS)
N3875103: C32.1 U5.A3(TR/SS)
N3875175: R9.1 U5.C1(RT)
N3875183: R8.1 U5.A2(FB)
N4006156: C38.2 C39.1 R16.4(2R1) RN1.1
N4006204: RN1.7 RN1.8 U10.3(INA+)
N4006242: R17.1 RN1.3 U10.1(OutA)
N4006254: C39.2 C42.1 R16.3(2R2) RN1.4
N4006270: RN1.5 RN1.6 U10.2(INA-)
N4021262: Q1.3(D) R?#1.2
N4037452: R22.1 SB3.2 SB5.2
N4044101: C46.2 C47.1 R21.4(2R1) RN2.1
N4044153: RN2.7 RN2.8 U10.5(INB+)
N4044191: RN2.3 SB5.1 U10.7(OutB)
N4044207: C47.2 C48.1 R21.3(2R2) RN2.4
N4044223: RN2.5 RN2.6 U10.6(INB-)

Not connected (* = marked no-connect by the designer): D3 1(NC)*; J2 6*; J4 3*; J5 6*; U1 5(PWM4H/RE7)* 8(AN18/T4CK/T9CK/RC3)* 9(AN19/T5CK/T8CK/RC4)* 17(TMS/RA0)* 18(AN20/~{FLTA}/INT1/RE8)* 19(AN21/~{FLTB}/INT2/RE9)* 20(AN5/QEB/CN7/RB5)* 21(AN4/QEA/CN6/RB4)* 32(AN8/RB8)* 33(AN9/RB9)* 38(TCK/RA1)* 41(AN12/RB12)* 42(AN13/RB13)* 43(AN14/RB14)* 44(AN15/OCFB/CN12/RB15)* 59(SDA2/RA3)* 60(TDI/RA4)* 61(TDO/RA5)* 66(INT3/RA14)* 67(INT4/RA15)* 68(IC1/RD8)* 69(IC2/RD9)* 70(IC3/RD10)* 71(IC4/RD11)* 72(OC1/RD0)* 76(OC2/RD1)* 91(AN22/CN22/RA6)* 92(AN23/CN23/RA7)* 96(RG12)* 97(RG13)*; U2 1(Vbias)*; U9 2(\~{INVALI}D)* 11(V+_1)* 12(V+_2)* 13(C1+)* 14(C1-)* 15(C2+)* 16(C2-)* 17(V-)*; U15 7(NC)*; U16 7(NC)*

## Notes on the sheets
sheet 1
- I2C expansion on
  daughtercard header
  see page 3
- PTH SENSOR
- EEPROM
- Bus Address = 1010000x
  x = 0 Write
  x = 1 Read
- Bus Address = 1110110x
  x = 0 Write
  x = 1 Read
sheet 2
- Primary Step Down Voltage = 3.45V
- Final System voltage = 3.3V
- Power Good Signal holds final until
  nearly charged
- Primary Step Down Voltage = 5.15V
- Final System voltage = 5.0V
- Power Good Signal holds final until
  nearly charged
- INPUT POWER
sheet 3
- COMPONENTS IN THIS NETWORK
  TO BE PLACED WITHIN 0.25" OF
  MCLR PIN
- REMOVE JUMPER
  FOR PROGRAMMING
- SECONDARY OSC
- ATTEMPT GUARD TRACES
  SEE DSPIC REFERENCE MANUAL
- PRIMARY OSC
- PLACE 0.1uF NEAR
  NUMBERED TERMINALS
  SAME SIDE AS IC
- 2
- 16
- 30
- 37
- 46
- 62
- 86
- 29
- 15
- 31
- 38
- 45
- 65
- 75
- 29
sheet 4
- BUS VOLTAGE ADJ:
  DNI FOR 5V CANBUS
  56.2K & 13.0K FOR 3.3V
- MPLAB ICD CONNECTOR
- CANBUS
- RS485
- SLEW RATE CONTROL: (RS PIN)
  RSL < 4K for high data rates
  Max 200K
- NOTE:
  FOR HEAVE CONE CONFIGURATION
  - DNI: U10, C40
  - Connect SB1 & SB2
- RS232
- DAUGHTERBOARD INTERFACE
sheet 5
- VIN1
  0-10VDC
- BATTERY HOUSING CONFIG:
  10K  1% PULLUP HERE
- REDUCE TO 3.3 or 3.0
  DEP ON VREF
- 100Hz LPF
- 100Hz LPF
- APPROXIMATE OUTPUT
  0-3.1 V
  0.8 mV / ADC COUNT @ 12-BIT
- VIN2
  0-10VDC
- BATTERY HOUSING CONFIG:
  10K  1% PULLUP HERE
- REDUCE TO 3.3 or 3.0
  DEP ON VREF
- 100Hz LPF
- APPROXIMATE OUTPUT
  0-3.1 V
  0.8 mV / ADC COUNT @ 12-BIT
- 100Hz LPF
- CIN1
  0-20mA 2-WIRE w/ FUSED 15V
- APPROXIMATE OUTPUT
  0.64 V  = 0 LBS
  3.20 V  = 10,000 LBS
  3.15 LBS / ADC COUNT @ 12-BIT
  OFFSET = 794 COUNTS
- 100Hz LPF
- CIN2
  0-20mA 4-WIRE
  SUPPLY 15-24VDC
- APPROXIMATE OUTPUT
  0 V  = 0 m
  3.20 V  = 2400 mm
   0.6 mm / ADC COUNT @ 12-BIT
- 100Hz LPF
- DO NOT LOAD
- FROM LASER RANGE FINDER
  (PRECONFIGURED MAX 2.4m)
  0 mA  =    0 m
  20mA = 2.4 m
sheet 6
- DIGITAL IO
- PWM
- MAX 1kHz
- 5V TOLERANT PINS
- CIN2 POWER SWITCHING
- MAX 1kHz
- Current Limiting Resistor:
  Rs = 50mV/Iset
  Iset =     1A
- MAX 1kHz
- Approximate self reset
  700ms without resistor.
- LOW SIDE SWITCHES (SSR DRIVERS?)
- Current Limiting Resistor:
  Rs = 50mV/Iset
  Iset =     1A
- AUXILIARY 15V
- Approximate self reset
  700ms without resistor.
sheet 7
- [HEAVE] 0-2V_DIFF INPUT FOR 0-48V
  [BATT] 0-2V_DIFF INPUT FOR 0-300V
- ACASA1002E3002P100:
  R1=R4=10K
  R2=R3=30K
- FILTER CUTOFF 2kHz, -72dB @ 16kHz
- BUS VOLTAGE = 0 to 400V
  VOUT = 0 to 3V pre-filter
- ANALOG VOLTAGE INPUTS
- 502Vbus=3Vinput
- CONNECT FOR SINGLE ENDED INPUT
  0-3.3V is ±50A IN BATTERY BOX USING ACS773
  DNI PARTS SHUNTED
- ACASA1002E3002P100:
  R1=R4=10K
  R2=R3=30K
- FILTER CUTOFF 2kHz, -72dB @ 16kHz
- [HEAVE] 0-2V_DIFF INPUT FOR 0-48V
  [BATT] DNS
- DNI RESISTOR
  FOR DIFF INPUT
